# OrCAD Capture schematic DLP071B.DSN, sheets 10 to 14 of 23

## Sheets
10 PAGE14 - TP, ARM JTAG, RESET: size A3
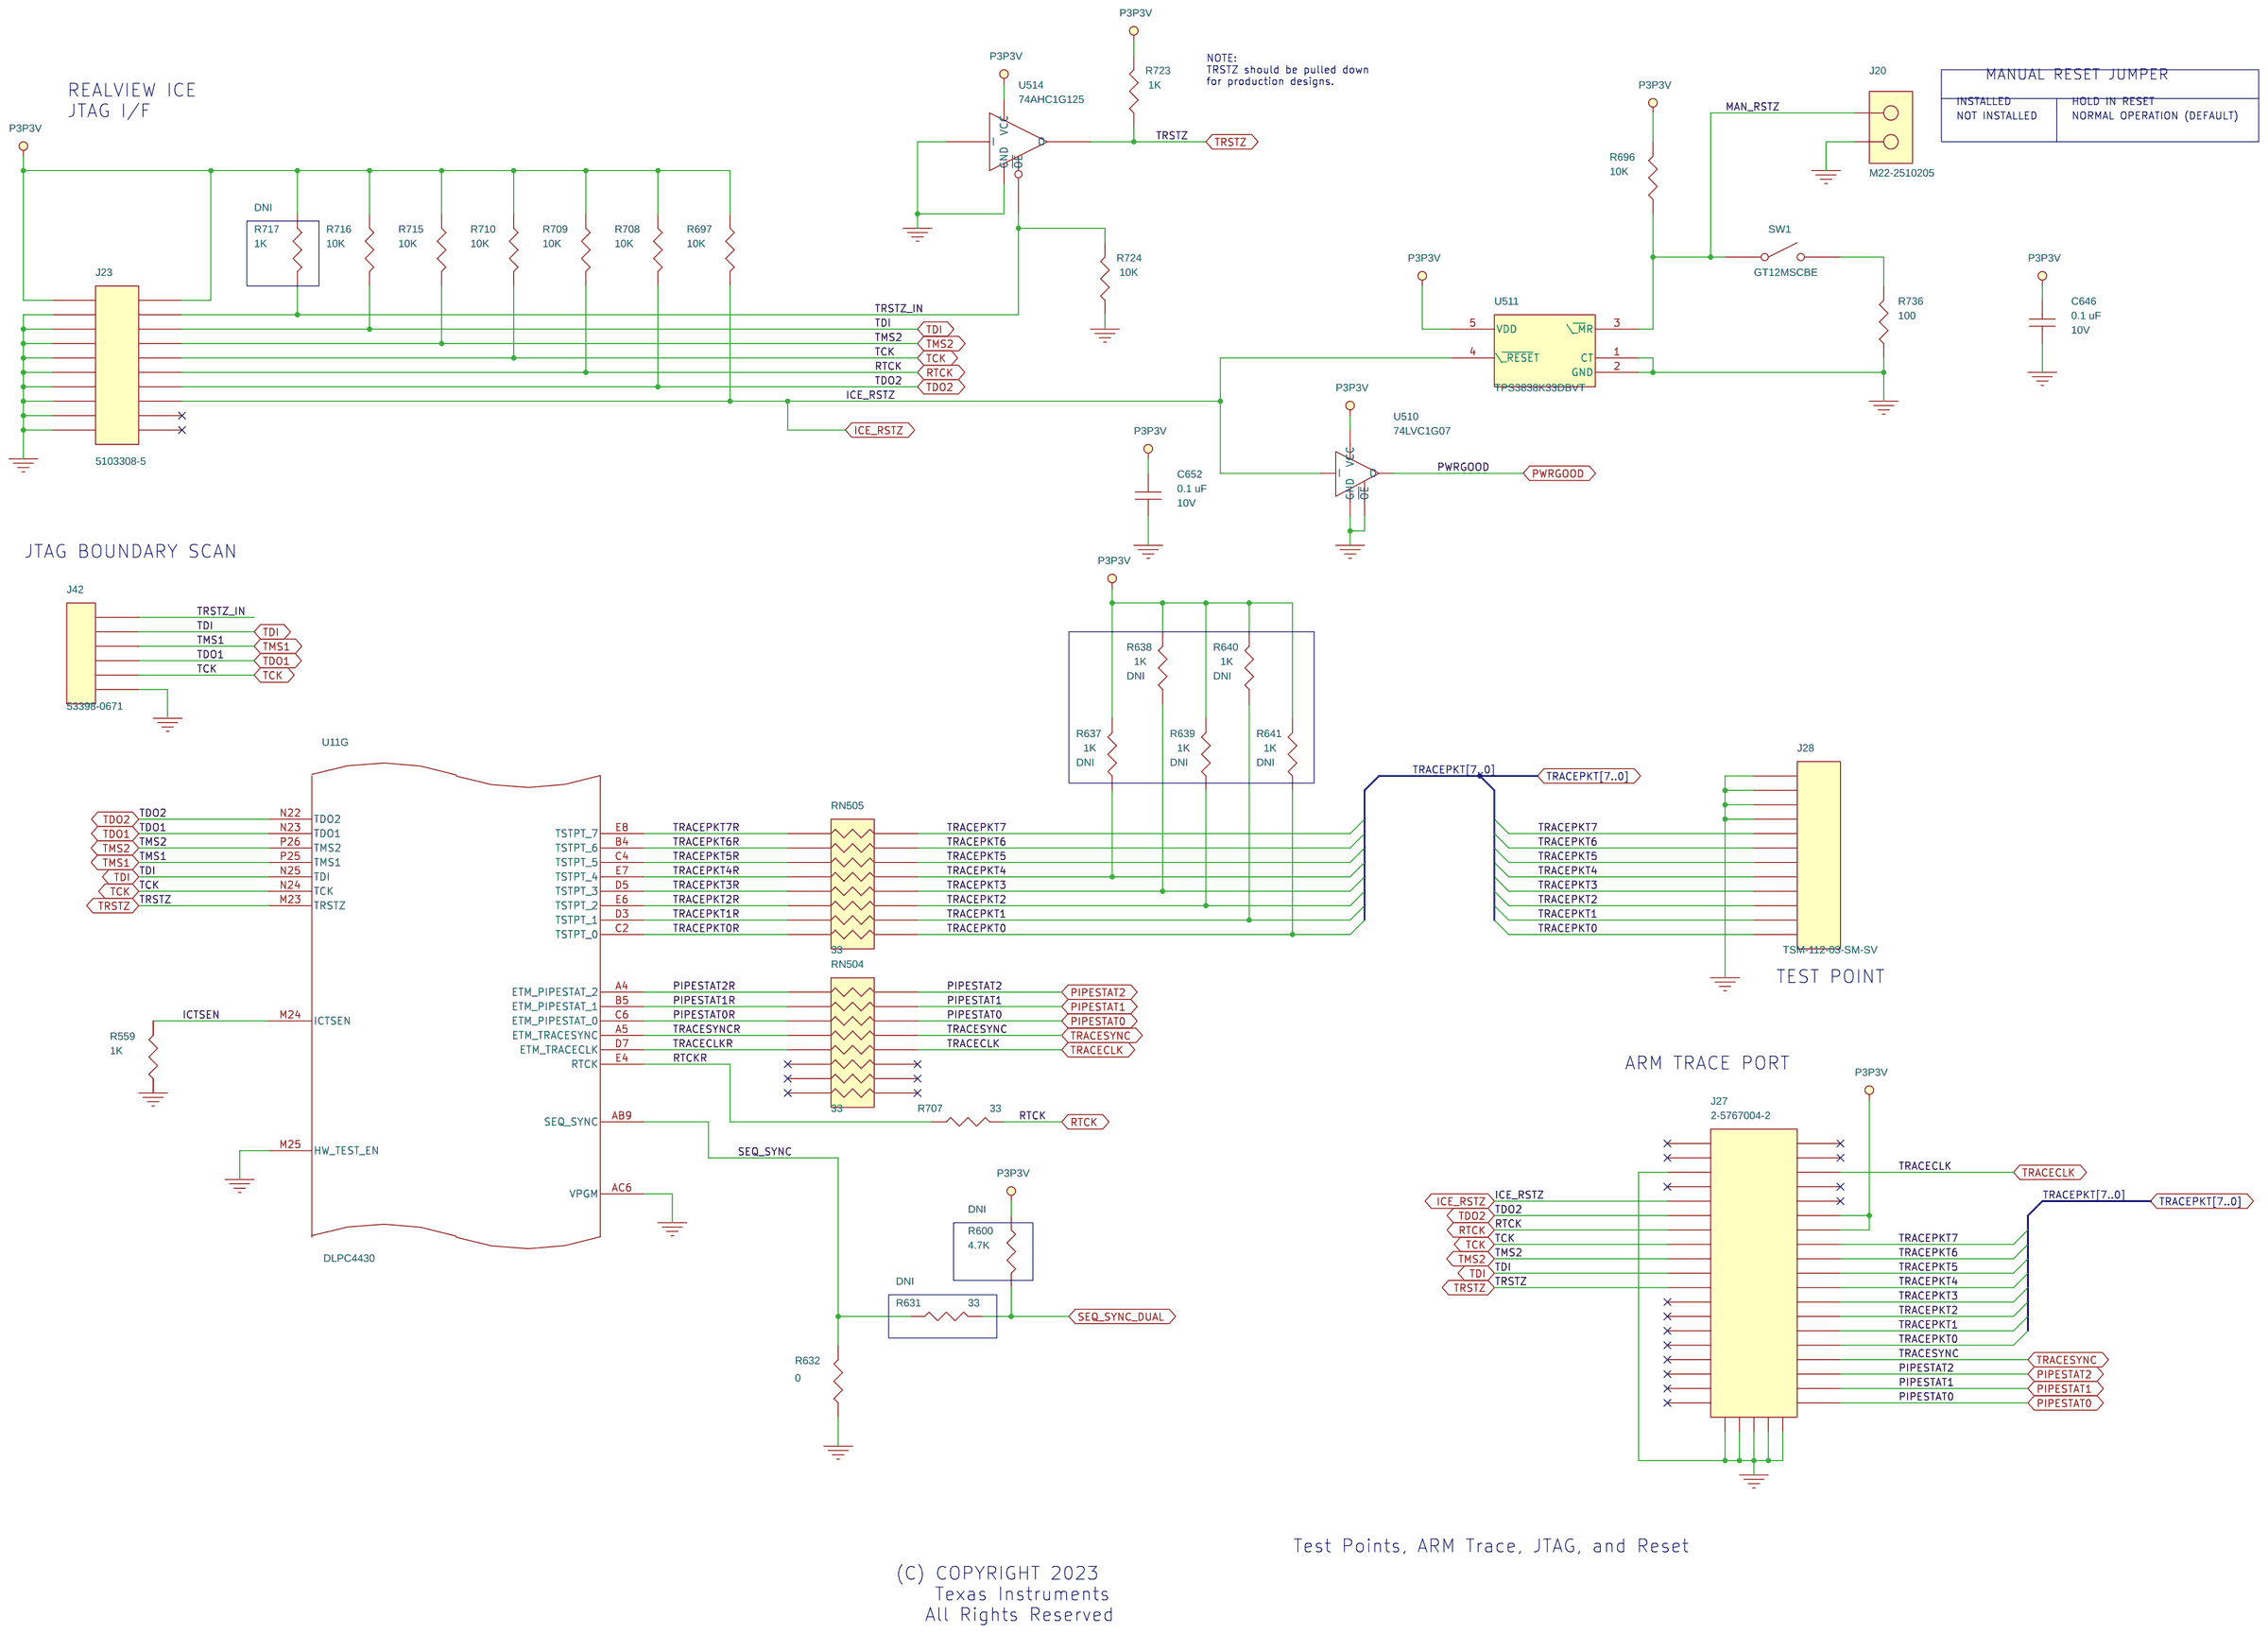
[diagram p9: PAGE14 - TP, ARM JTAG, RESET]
11 PAGE13 - GPIO EXP & KEYBRD: size A3
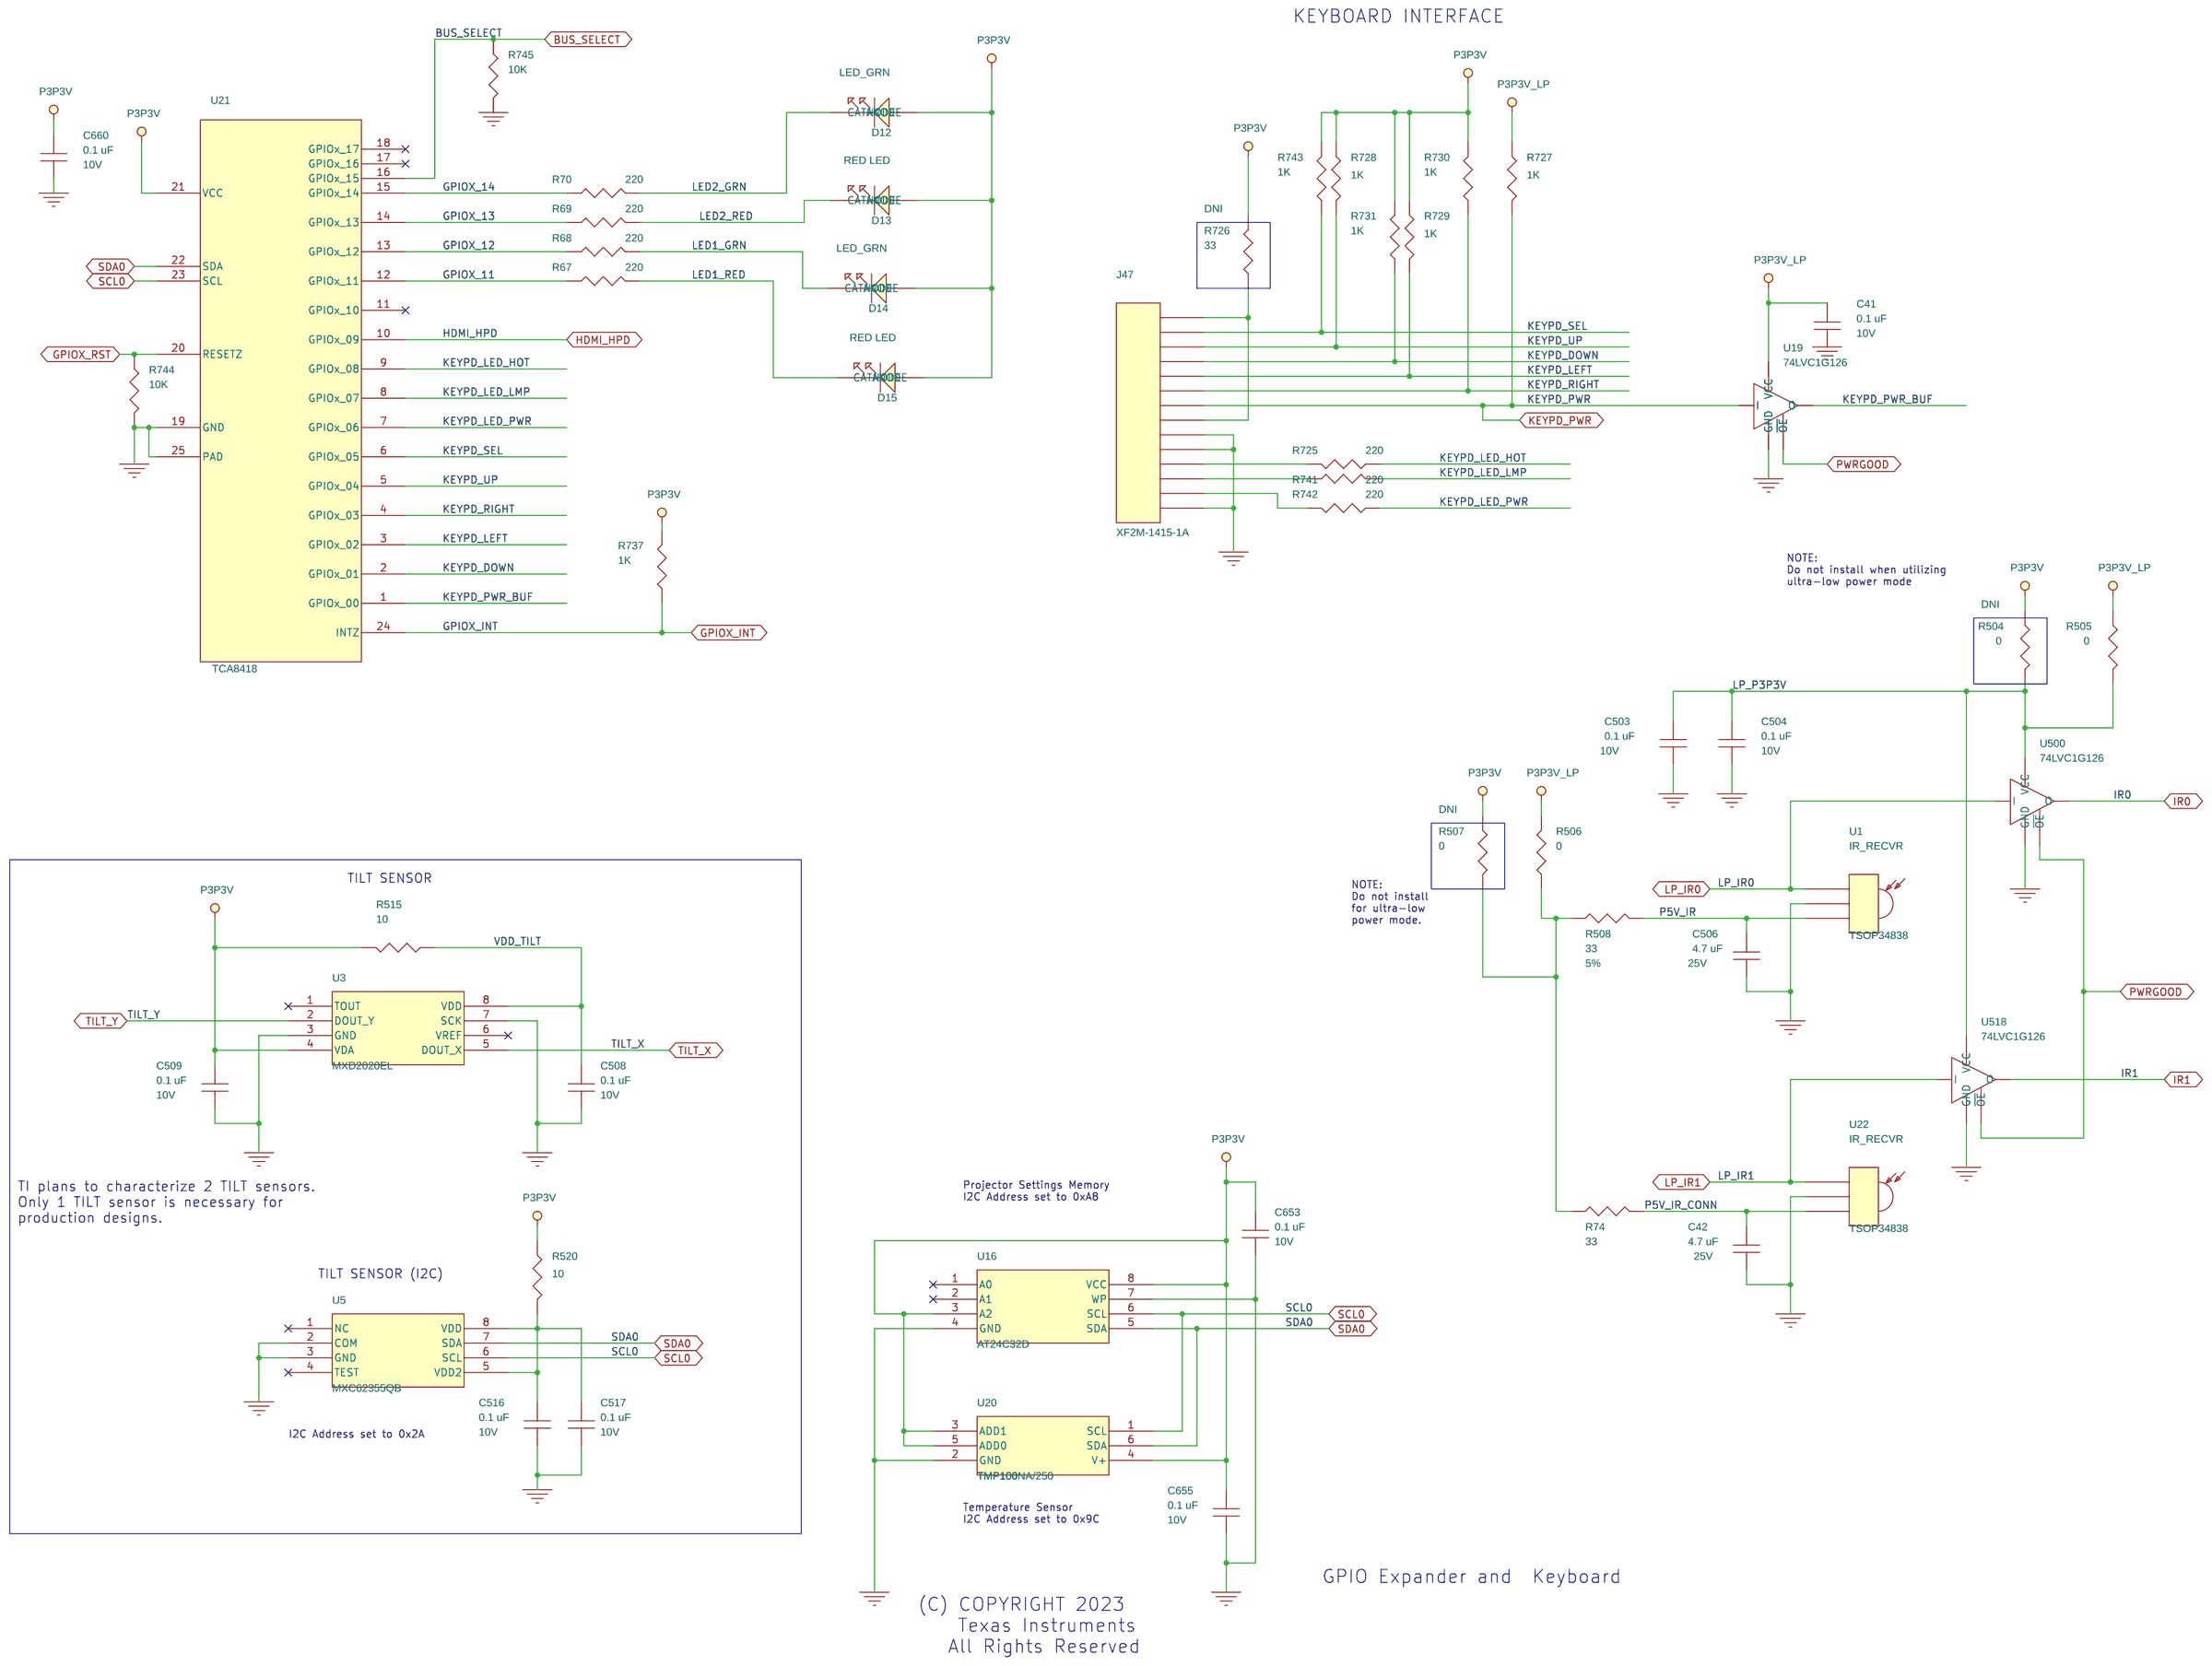
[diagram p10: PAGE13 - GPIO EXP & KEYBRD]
12 PAGE12 - GPIO, I2C, BALLAST: size A3
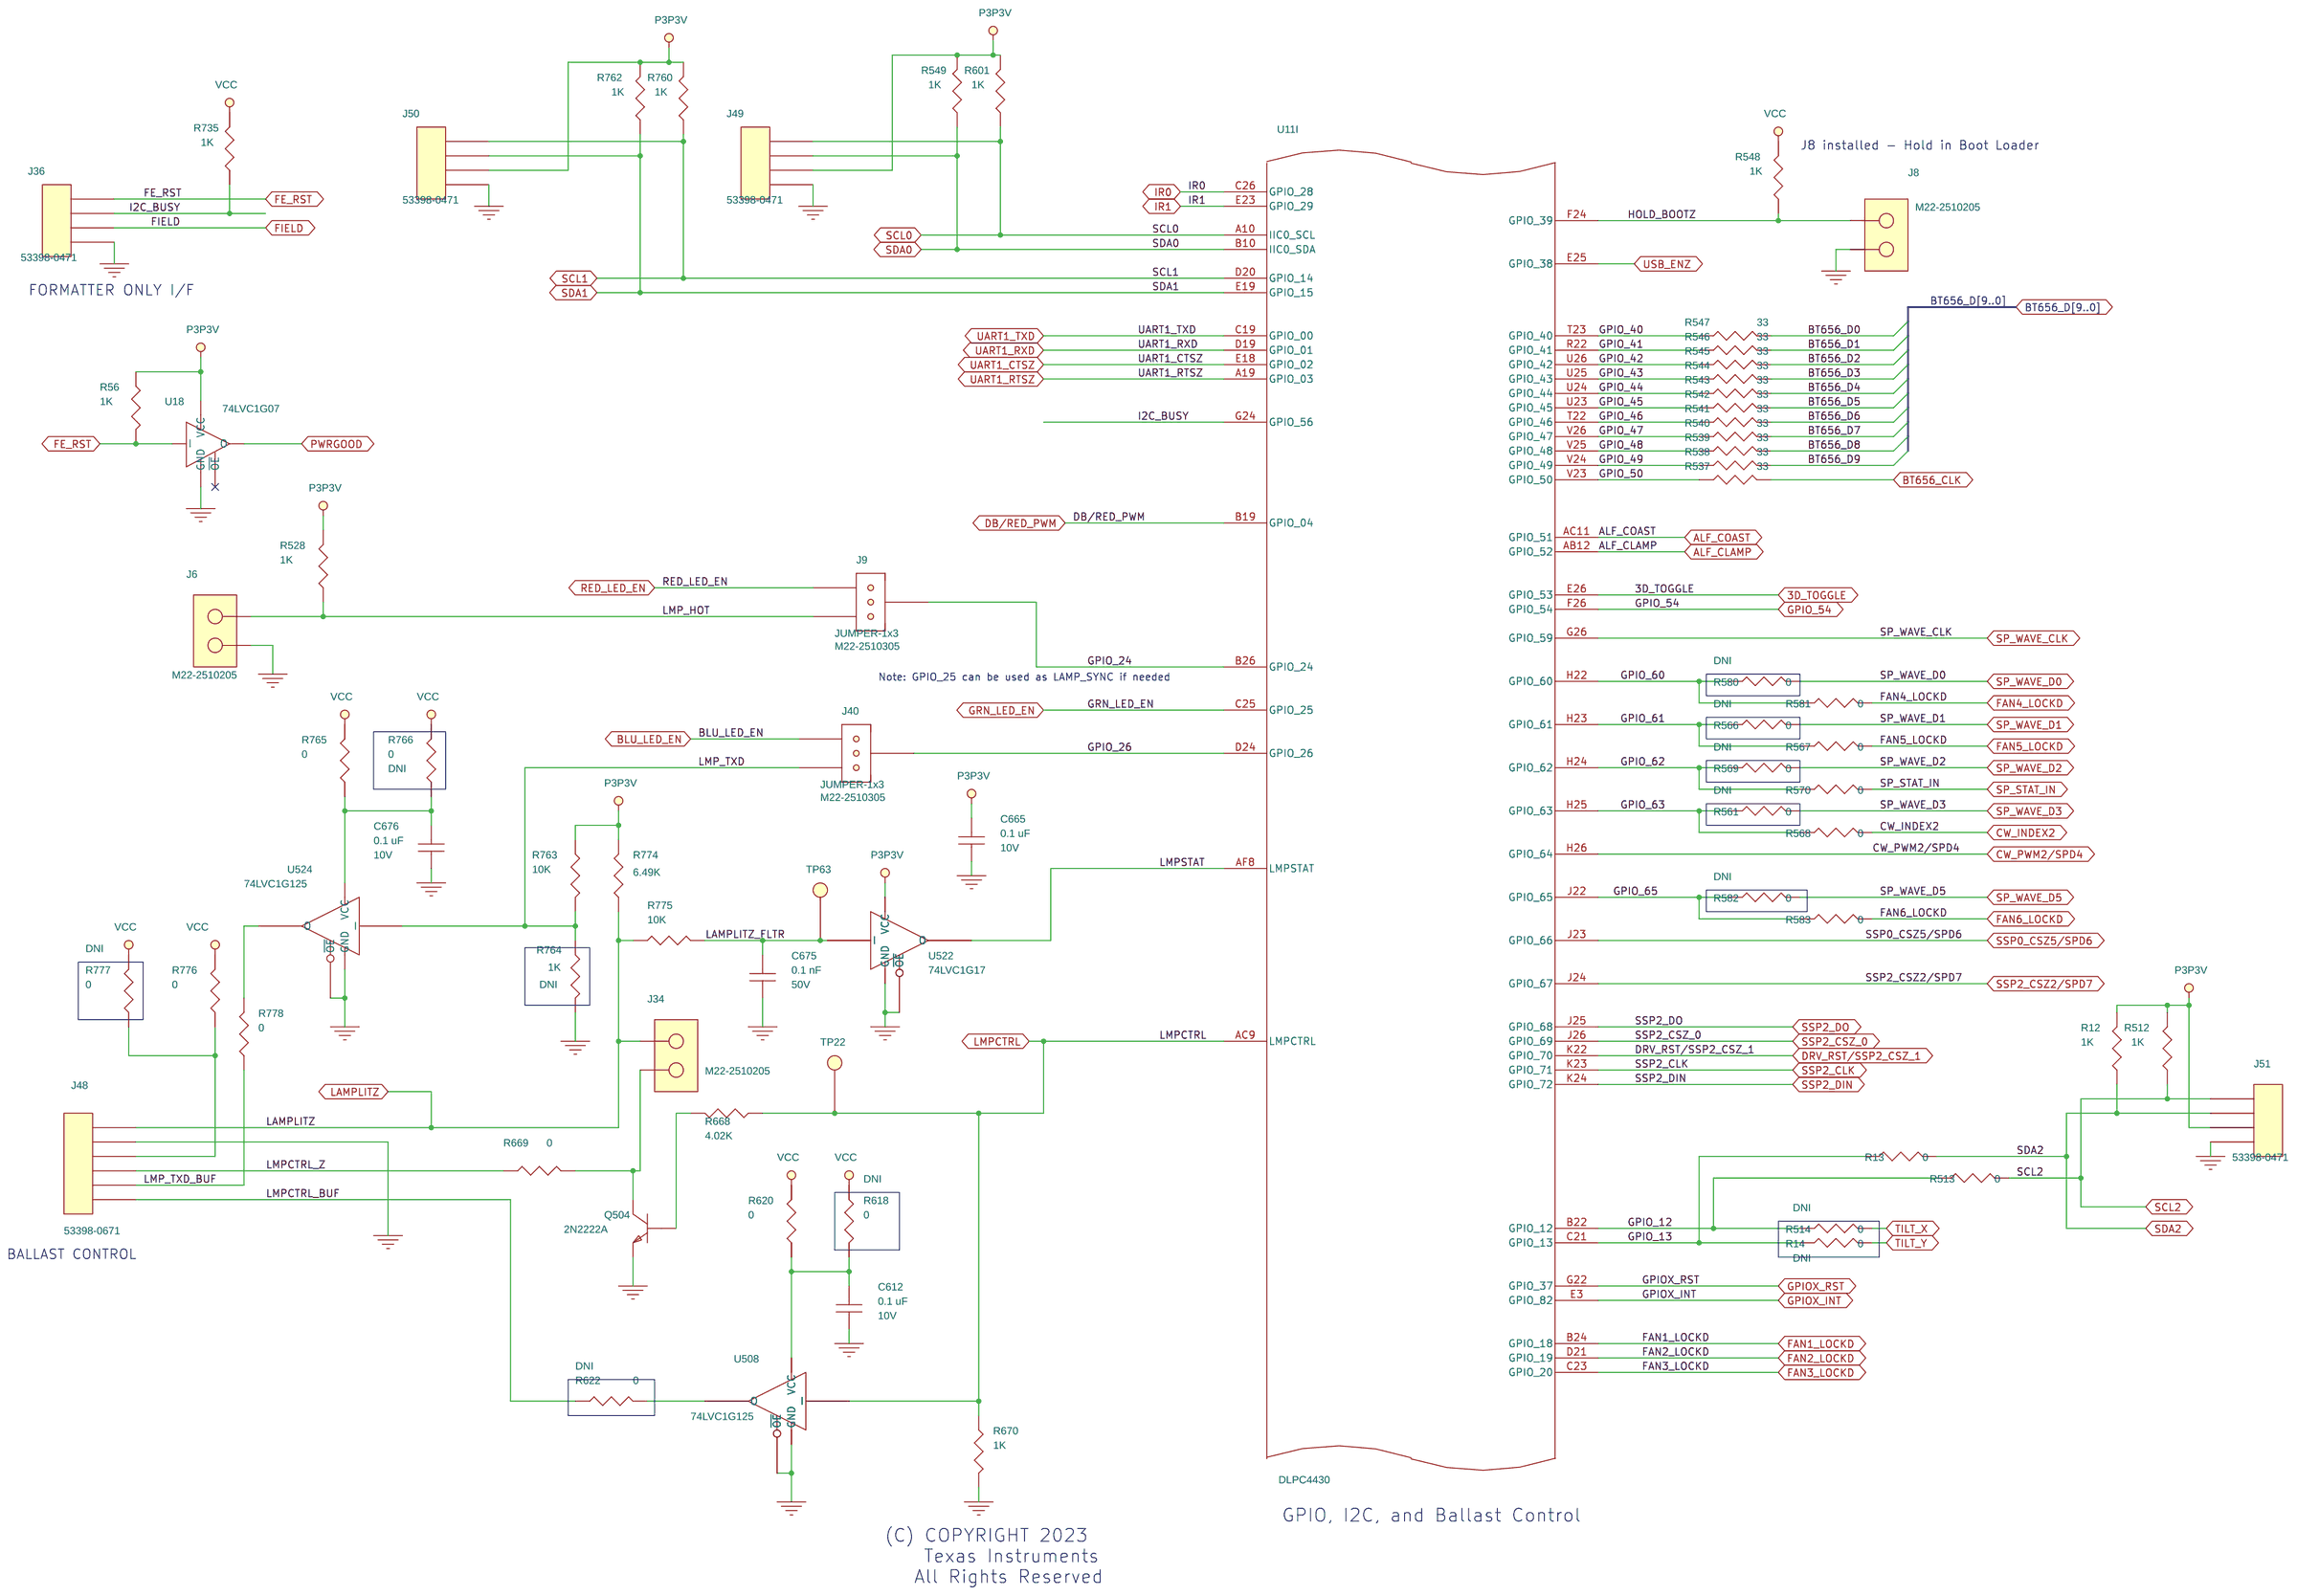
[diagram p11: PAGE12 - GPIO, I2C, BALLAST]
13 PAGE11 - FAN, CW INT & PERIPHLS: size A3
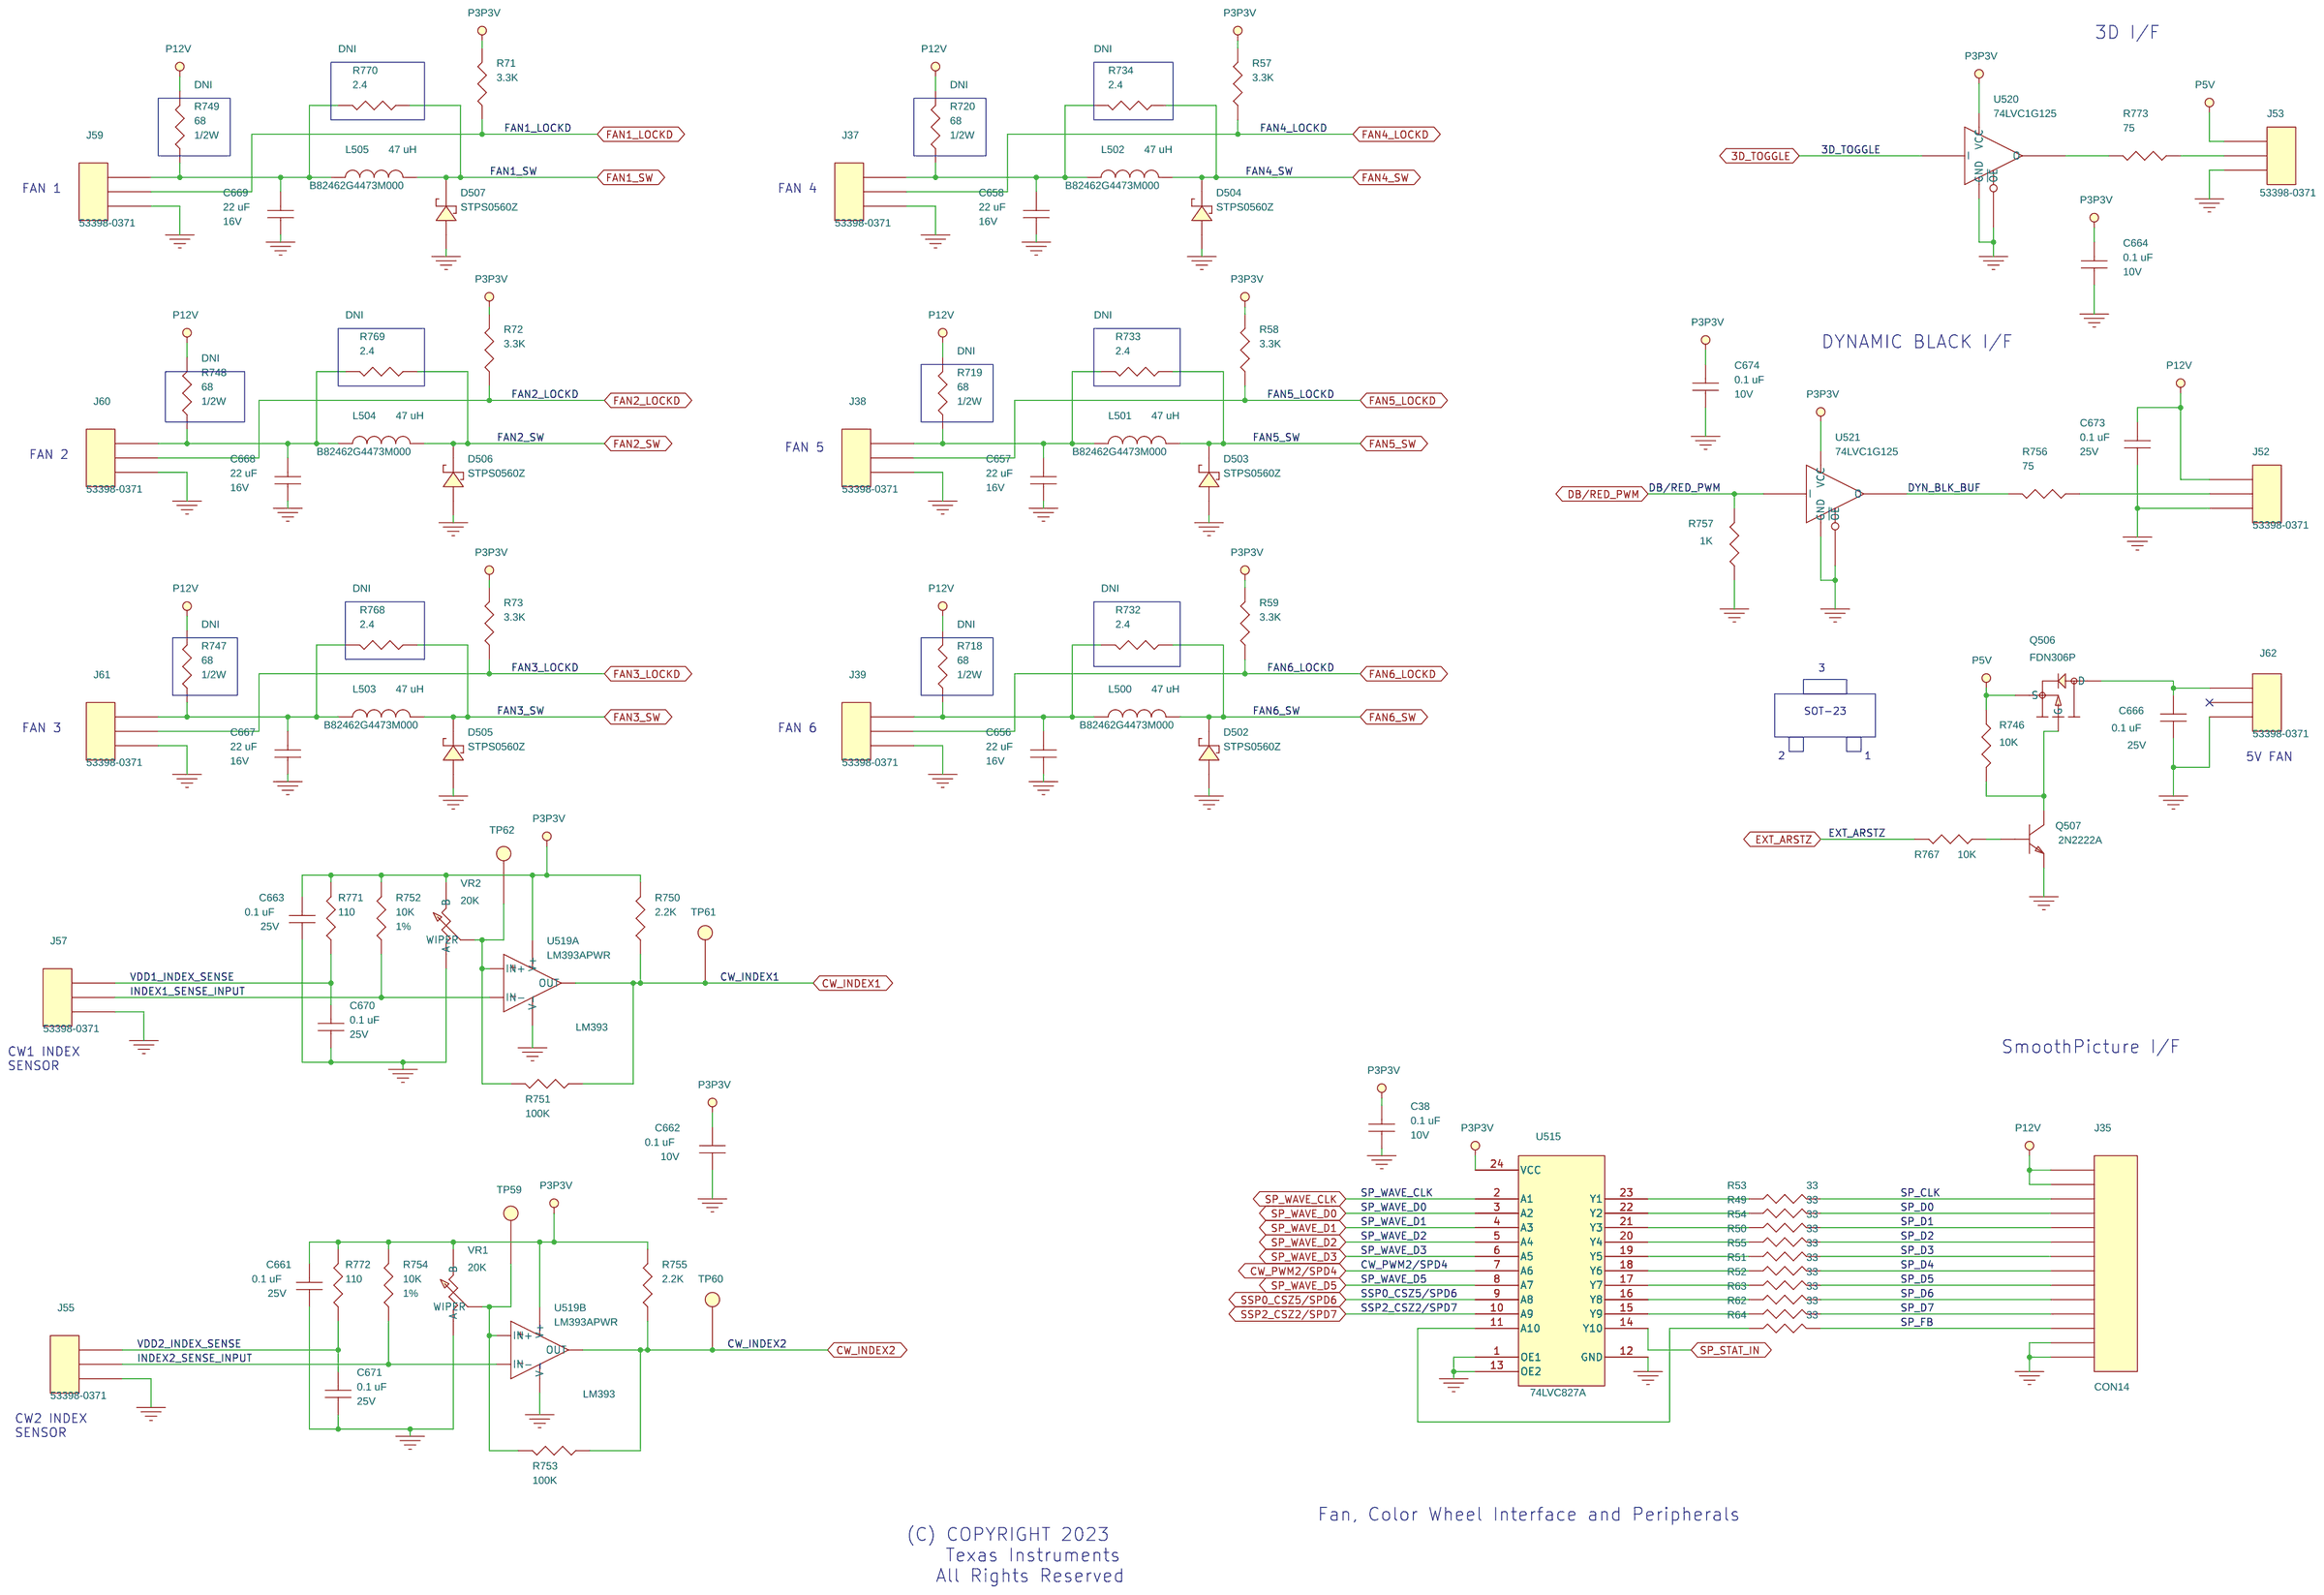
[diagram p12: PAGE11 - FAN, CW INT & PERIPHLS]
14 PAGE10 - COLOR WHEEL DRIVE: size A3
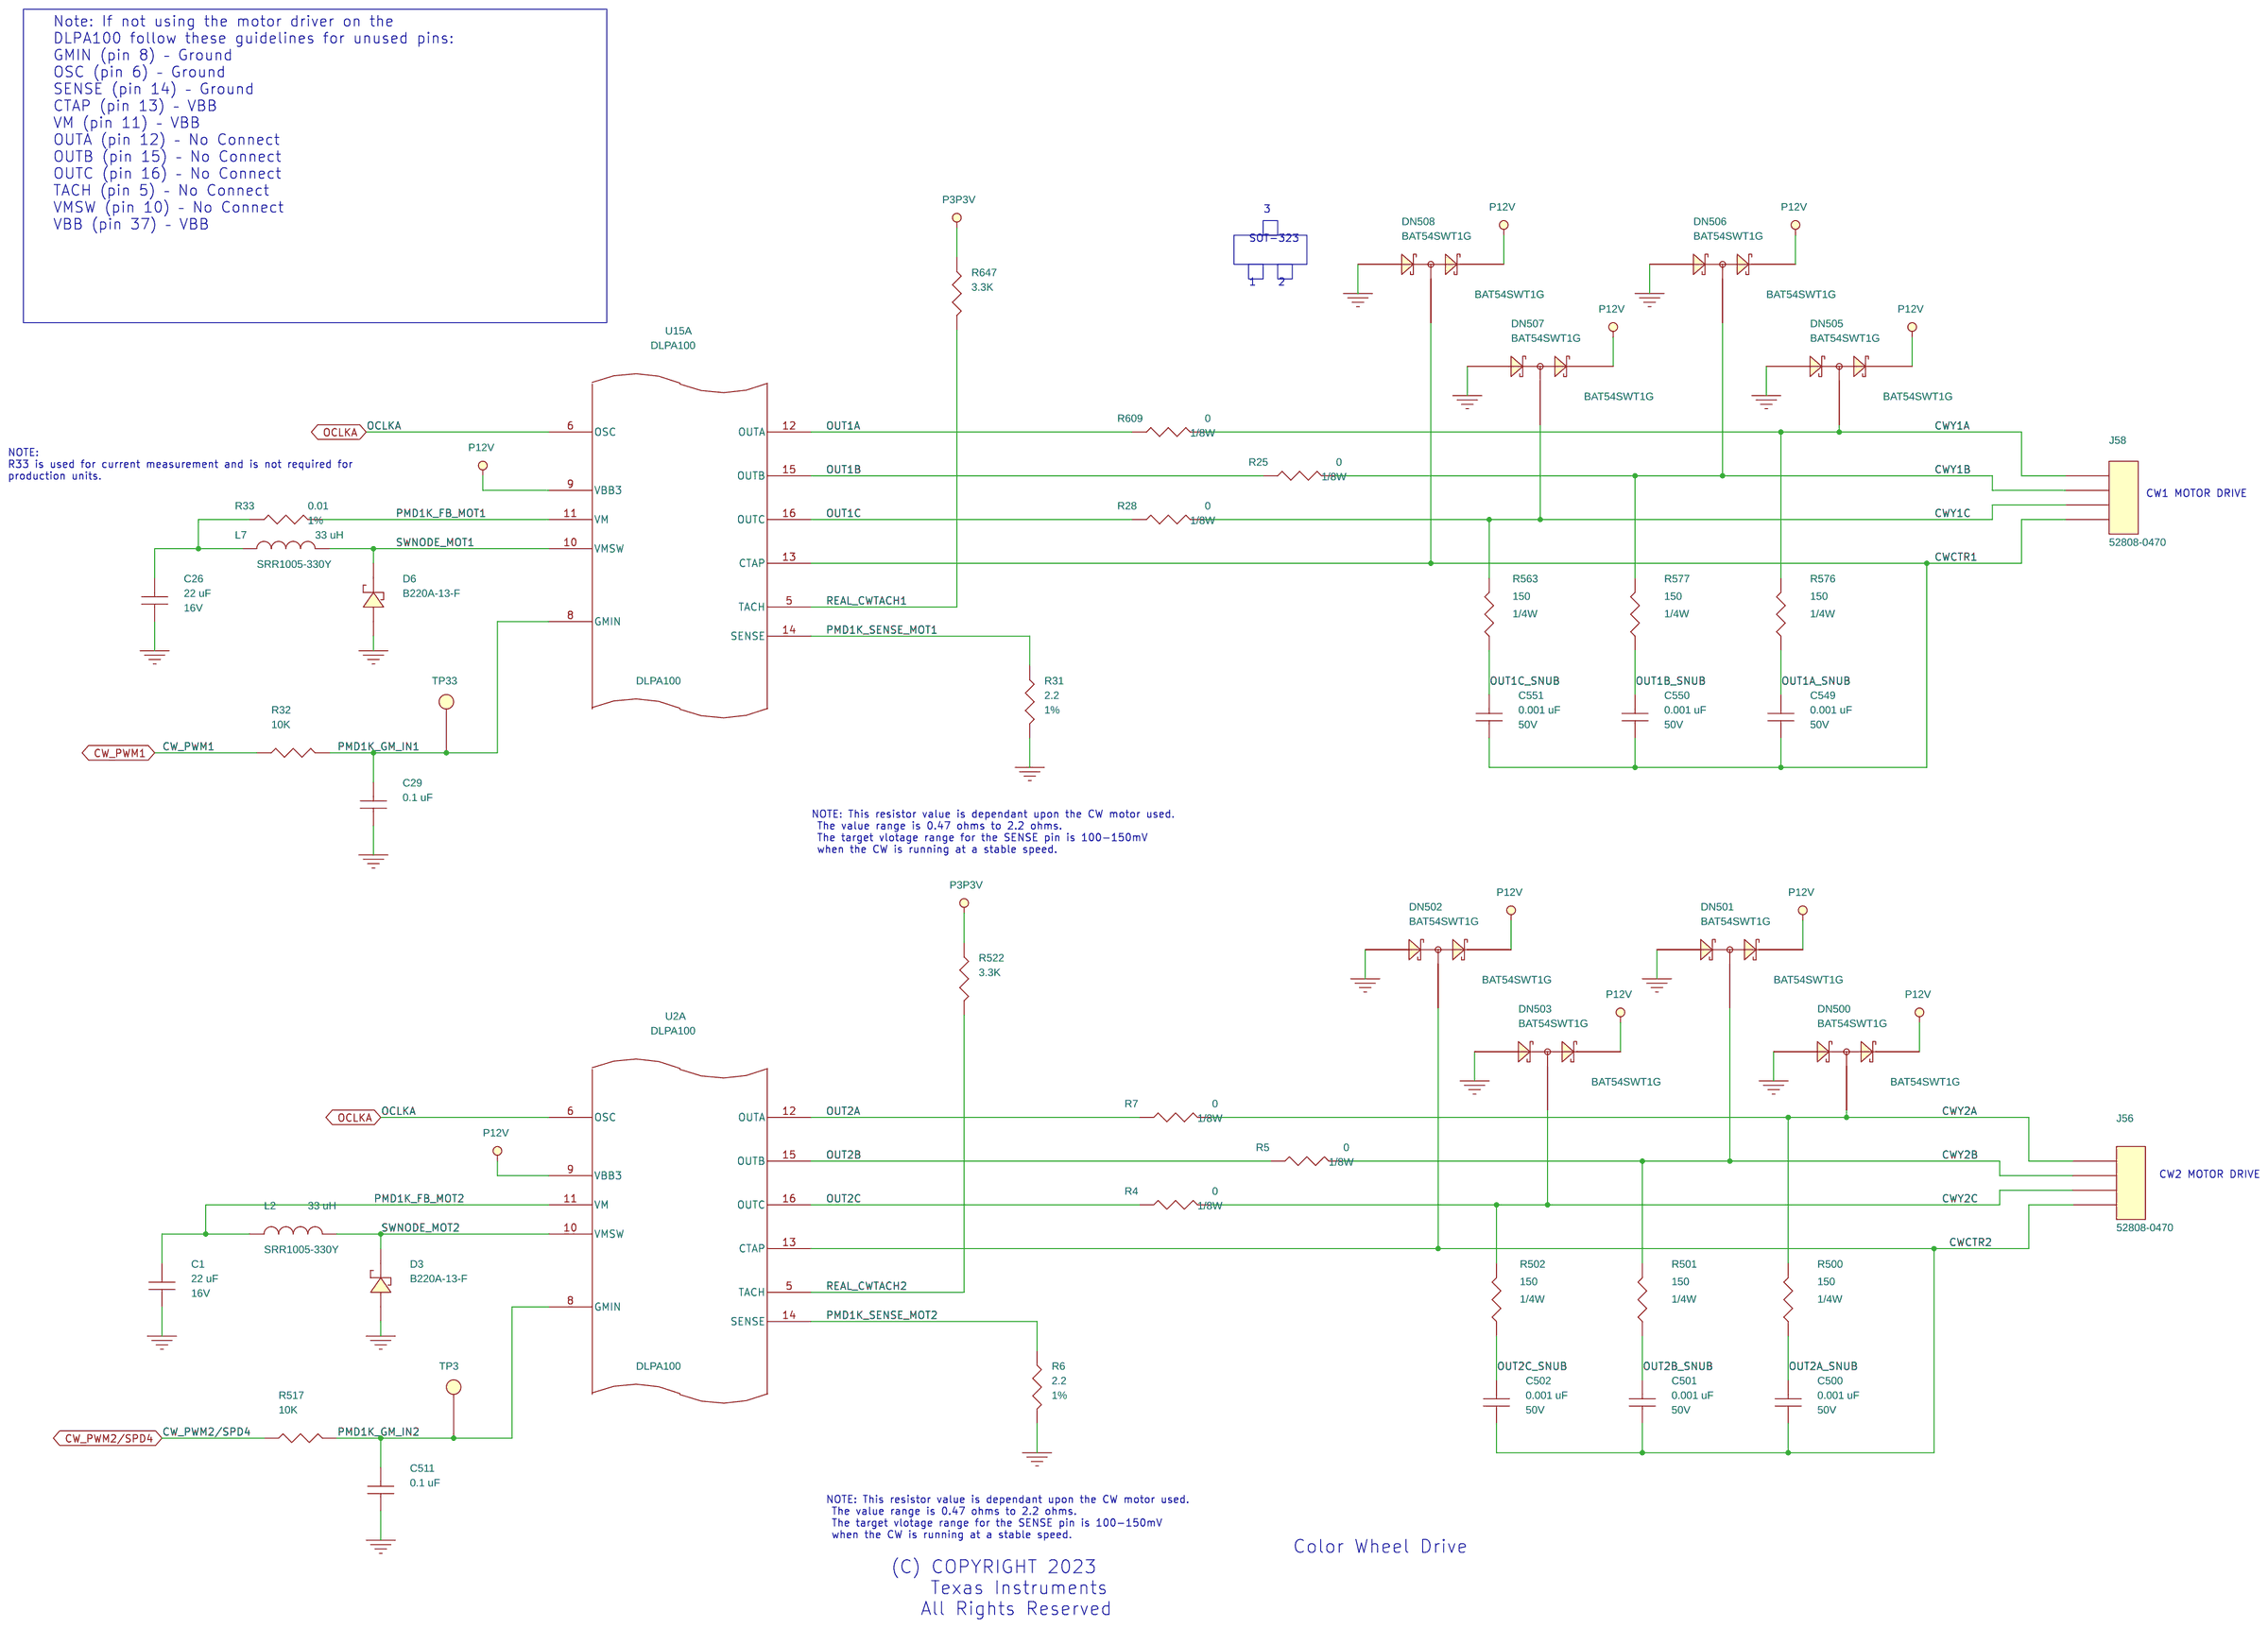
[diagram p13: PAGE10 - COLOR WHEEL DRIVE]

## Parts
sheet PAGE08 - DLPA100 POWER SUPPLIES
U15  DLPA100  [QF48_PPAD]  (sections A,B,C)
sheet PAGE09 - 2ND PMD POWER SUPPLIES
U2  DLPA100  [QF48_PPAD]  (sections A,B,C)
sheet PAGE10 - COLOR WHEEL DRIVE
C1  22 uF  [CAP_1210]
C26  22 uF  [CAP_1210]
C29  0.1 uF  [CAP_0402]
C500  0.001 uF  [CAP_0805]
C501  0.001 uF  [CAP_0805]
C502  0.001 uF  [CAP_0805]
C511  0.1 uF  [CAP_0402]
C549  0.001 uF  [CAP_0805]
C550  0.001 uF  [CAP_0805]
C551  0.001 uF  [CAP_0805]
D3  B220A  [DIO-SMA]
D6  B220A  [DIO-SMA]
DN500  BAT54SWT1G  [SOT_323]
DN501  BAT54SWT1G  [SOT_323]
DN502  BAT54SWT1G  [SOT_323]
DN503  BAT54SWT1G  [SOT_323]
DN505  BAT54SWT1G  [SOT_323]
DN506  BAT54SWT1G  [SOT_323]
DN507  BAT54SWT1G  [SOT_323]
DN508  BAT54SWT1G  [SOT_323]
J56  CON4  [CONN4-52808_MOLEX]
J58  CON4  [CONN4-52808_MOLEX]
L2  33 uH  [IND_SRR1005]
L7  33 uH  [IND_SRR1005]
R4  0  [RES_0805]
R5  0  [RES_0805]
R6  2.2  [RES_1206]
R7  0  [RES_0805]
R25  0  [RES_0805]
R28  0  [RES_0805]
R31  2.2  [RES_1206]
R32  10K  [RES_0402]
R33  0.01  [RES_0805]
R500  150  [RES_1206]
R501  150  [RES_1206]
R502  150  [RES_1206]
R517  10K  [RES_0402]
R522  3.3K  [RES_0402]
R563  150  [RES_1206]
R576  150  [RES_1206]
R577  150  [RES_1206]
R609  0  [RES_0805]
R647  3.3K  [RES_0402]
TP3  Testpoint  [TP]
TP33  Testpoint  [TP]
sheet PAGE11 - FAN, CW INT & PERIPHLS
C38  0.1 uF  [CAP_0402]
C656  22 uF  [CAP_1210]
C657  22 uF  [CAP_1210]
C658  22 uF  [CAP_1210]
C661  0.1 uF  [CAP_0603]
C662  0.1 uF  [CAP_0402]
C663  0.1 uF  [CAP_0603]
C664  0.1 uF  [CAP_0402]
C666  0.1 uF  [CAP_0603]
C667  22 uF  [CAP_1210]
C668  22 uF  [CAP_1210]
C669  22 uF  [CAP_1210]
C670  0.1 uF  [CAP_0603]
C671  0.1 uF  [CAP_0603]
C673  0.1 uF  [CAP_0603]
C674  0.1 uF  [CAP_0402]
D502  STPS0560Z  [SOD-123]
D503  STPS0560Z  [SOD-123]
D504  STPS0560Z  [SOD-123]
D505  STPS0560Z  [SOD-123]
D506  STPS0560Z  [SOD-123]
D507  STPS0560Z  [SOD-123]
J35  CON14  [CONN14-53047_MLX]
J37  CON3  [CN3_53398_MOLEX]
J38  CON3  [CN3_53398_MOLEX]
J39  CON3  [CN3_53398_MOLEX]
J52  CON3  [CN3_53398_MOLEX]
J53  CON3  [CN3_53398_MOLEX]
J55  CON3  [CN3_53398_MOLEX]
J57  CON3  [CN3_53398_MOLEX]
J59  CON3  [CN3_53398_MOLEX]
J60  CON3  [CN3_53398_MOLEX]
J61  CON3  [CN3_53398_MOLEX]
J62  CON3  [CN3_53398_MOLEX]
L500  47 uH  [IND_SERH]
L501  47 uH  [IND_SERH]
L502  47 uH  [IND_SERH]
L503  47 uH  [IND_SERH]
L504  47 uH  [IND_SERH]
L505  47 uH  [IND_SERH]
Q506  FDN306P  [SOT23-3_FC]
Q507  2N2222A  [SOT23AVXD]
R49  33  [RES_0402]
R50  33  [RES_0402]
R51  33  [RES_0402]
R52  33  [RES_0402]
R53  33  [RES_0402]
R54  33  [RES_0402]
R55  33  [RES_0402]
R57  3.3K  [RES_0402]
R58  3.3K  [RES_0402]
R59  3.3K  [RES_0402]
R62  33  [RES_0402]
R63  33  [RES_0402]
R64  33  [RES_0402]
R71  3.3K  [RES_0402]
R72  3.3K  [RES_0402]
R73  3.3K  [RES_0402]
R718  68  [RES_1210]
R719  68  [RES_1210]
R720  68  [RES_1210]
R732  2.4  [RES_1210]
R733  2.4  [RES_1210]
R734  2.4  [RES_1210]
R746  10K  [RES_0402]
R747  68  [RES_1210]
R748  68  [RES_1210]
R749  68  [RES_1210]
R750  2.2K  [RES_0603]
R751  100K  [RES_0402]
R752  10K  [RES_0402]
R753  100K  [RES_0402]
R754  10K  [RES_0402]
R755  2.2K  [RES_0603]
R756  75  [RES_0603]
R757  1K  [RES_0402]
R767  10K  [RES_0402]
R768  2.4  [RES_1210]
R769  2.4  [RES_1210]
R770  2.4  [RES_1210]
R771  110  [RES_0805]
R772  110  [RES_0805]
R773  75  [RES_0603]
TP59  Testpoint  [TP]
TP60  Testpoint  [TP]
TP61  Testpoint  [TP]
TP62  Testpoint  [TP]
U515  74LVC827A  [SOIC24-PW_TI]
U519  LM393  [SOIC8-PW_TI]  (sections A,B)
U520  74LVC1G125  [SOT23-DBV_TI]
U521  74LVC1G125  [SOT23-DBV_TI]
VR1  20K  [POT-3314G]
VR2  20K  [POT-3314G]
sheet PAGE12 - GPIO, I2C, BALLAST
C612  0.1 uF  [CAP_0402]
C665  0.1 uF  [CAP_0402]
C675  0.1 nF  [CAP_0603]
C676  0.1 uF  [CAP_0402]
J6  HDR_2  [HDR2_2MM]
J8  HDR_2  [HDR2_2MM]
J9  JUMPER-1x3  [HDR1X3-TMM1030X-X-S_SAM]
J34  HDR_2  [HDR2_2MM]
J36  CONN_4  [CONN4-53398-a_MOLEX]
J40  JUMPER-1x3  [HDR1X3-TMM1030X-X-S_SAM]
J48  CON6  [CONN6-53398-0690-a_MOLEX]
J49  CONN_4  [CONN4-53398-a_MOLEX]
J50  CONN_4  [CONN4-53398-a_MOLEX]
J51  CONN_4  [CONN4-53398-a_MOLEX]
Q504  2N2222A  [SOT23AVXD]
R12  1K  [RES_0402]
R13  0  [RES_0402]
R14  0  [RES_0402]
R56  1K  [RES_0402]
R512  1K  [RES_0402]
R513  0  [RES_0402]
R514  0  [RES_0402]
R528  1K  [RES_0402]
R537  33  [RES_0402]
R538  33  [RES_0402]
R539  33  [RES_0402]
R540  33  [RES_0402]
R541  33  [RES_0402]
R542  33  [RES_0402]
R543  33  [RES_0402]
R544  33  [RES_0402]
R545  33  [RES_0402]
R546  33  [RES_0402]
R547  33  [RES_0402]
R548  1K  [RES_0402]
R549  1K  [RES_0402]
R561  0  [RES_0402]
R566  0  [RES_0402]
R567  0  [RES_0402]
R568  0  [RES_0402]
R569  0  [RES_0402]
R570  0  [RES_0402]
R580  0  [RES_0402]
R581  0  [RES_0402]
R582  0  [RES_0402]
R583  0  [RES_0402]
R601  1K  [RES_0402]
R618  0  [RES_0402]
R620  0  [RES_0402]
R622  0  [RES_0402]
R668  4.02K  [RES_0603]
R669  0  [RES_0402]
R670  1K  [RES_0402]
R735  1K  [RES_0402]
R760  1K  [RES_0402]
R762  1K  [RES_0402]
R763  10K  [RES_0402]
R764  1K  [RES_0402]
R765  0  [RES_0402]
R766  0  [RES_0402]
R774  6.49K  [RES_0402]
R775  10K  [RES_0402]
R776  0  [RES_0402]
R777  0  [RES_0402]
R778  0  [RES_0402]
TP22  Testpoint  [TP]
TP63  Testpoint  [TP]
U18  74LVC1G07  [SOT23-DBV_TI]
U508  74LVC1G125  [SOT23-DBV_TI]
U522  74LVC1G17  [SOT23-DBV_TI]
U524  74LVC1G125  [SOT23-DBV_TI]
sheet PAGE13 - GPIO EXP & KEYBRD
C41  0.1 uF  [CAP_0402]
C42  4.7 uF  [CAP_0805]
C503  0.1 uF  [CAP_0402]
C504  0.1 uF  [CAP_0402]
C506  4.7 uF  [CAP_0805]
C508  0.1 uF  [CAP_0402]
C509  0.1 uF  [CAP_0402]
C516  0.1 uF  [CAP_0402]
C517  0.1 uF  [CAP_0402]
C653  0.1 uF  [CAP_0402]
C655  0.1 uF  [CAP_0402]
C660  0.1 uF  [CAP_0402]
D12  LED_GRN  [LED-0402-REV]
D13  RED LED  [LED-0402-REV]
D14  LED_GRN  [LED-0402-REV]
D15  RED LED  [LED-0402-REV]
J47  CON14  [conn14-xf2m-a_omron]
R67  220  [RES_0603]
R68  220  [RES_0603]
R69  220  [RES_0603]
R70  220  [RES_0603]
R74  33  [RES_0402]
R504  0  [RES_0402]
R505  0  [RES_0402]
R506  0  [RES_0402]
R507  0  [RES_0402]
R508  33  [RES_0402]
R515  10  [RES_0603]
R520  10  [RES_0603]
R725  220  [RES_0603]
R726  33  [RES_0402]
R727  1K  [RES_0402]
R728  1K  [RES_0402]
R729  1K  [RES_0402]
R730  1K  [RES_0402]
R731  1K  [RES_0402]
R737  1K  [RES_0402]
R741  220  [RES_0603]
R742  220  [RES_0603]
R743  1K  [RES_0402]
R744  10K  [RES_0402]
R745  10K  [RES_0402]
U1  IR_RECVR  [VISHAY_IR_TSOP348]
U3  TILT  [LCC8-MXD2125_MEMSIC]
U5  TILT_I2C  [LCC8-MXD2125_MEMSIC]
U16  AT24C32D  [TSSOP_8]
U19  74LVC1G126  [SOT23-DBV_TI]
U20  TMP100  [SOIC6-DBV_TI]
U21  TCA8418  [PQFP24-QFN-25_SI]
U22  IR_RECVR  [VISHAY_IR_TSOP348]
U500  74LVC1G126  [SOT23-DBV_TI]
U518  74LVC1G126  [SOT23-DBV_TI]
sheet PAGE14 - TP, ARM JTAG, RESET
C646  0.1 uF  [CAP_0402]
C652  0.1 uF  [CAP_0402]
J20  HDR_2  [HDR2_2MM]
J23  CON20A  [HDR10X2-5103308_TYCO]
J27  ARM_TRACE_PORT  [MICTOR_HPA]
J28  CON12  [CONN12-SMT-TSM-112-SV_SAMTEC]
J42  CON6  [CONN6-53398-0690-a_MOLEX]
R559  1K  [RES_0402]
R600  4.7K  [RES_0402]
R631  33  [RES_0402]
R632  0  [RES_0402]
R637  1K  [RES_0402]
R638  1K  [RES_0402]
R639  1K  [RES_0402]
R640  1K  [RES_0402]
R641  1K  [RES_0402]
R696  10K  [RES_0402]
R697  10K  [RES_0402]
R707  33  [RES_0402]
R708  10K  [RES_0402]
R709  10K  [RES_0402]
R710  10K  [RES_0402]
R715  10K  [RES_0402]
R716  10K  [RES_0402]
R717  1K  [RES_0402]
R723  1K  [RES_0402]
R724  10K  [RES_0402]
R736  100  [RES_0402]
RN504  33  [RNET16-EXB-2HV_PAN]
RN505  33  [RNET16-EXB-2HV_PAN]
SW1  SW SPST  [SW_GT12]
U510  74LVC1G07  [SOT23-DBV_TI]
U511  TPS3838  [SOT23-DBV_TI]
U514  74AHC1G125  [SOT23-DBV_TI]
sheet PAGE15 - RS-232, SSP, USB
U11  DLPC4430  [BGA552-DDP4422_TI_MOD]  (sections A,B,C,D,E,F,G,H,I,J)

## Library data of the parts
U2 U15 = PMD1000_0: IC, Power and Motor Driver; MFG: TI; SOURCE: PROVIDED BY TI
C1 C26 C656-C658 C667-C669 = CAP_NP: Capacitor; MFG: MURATA; Part Number: GRM32ER61C226KE20L; RATING: 16V; SOURCE: DIGI 490-1882-2-ND; TOLERANCE: 10%; Type: X5R
C29 C38 C41 C503 C504 C508 C509 C511 C516 C517 C612 C646 C652 C653 C655 C660 C662 C664 C665 C674 C676 = CAP_NP: Capacitor; MFG: KEMET; Part Number: C0402C104K8RACTU; RATING: 10V; SOURCE: DIGI 399-3520-1-ND; TOLERANCE: 10%; Type: X7R
C500-C502 C549-C551 = CAP_NP: Capacitor; MFG: AVX; Part Number: 08055C102KAT2A; RATING: 50V; SOURCE: DIGI 478-1371-1-ND; TOLERANCE: 10%; Type: X7R
D3 D6 = DIODE_SCHOTTKY: Diode, Schottky; MFG: DIODES INC; Part Number: B220A-13-F; RATING: 20V, 2A; SOURCE: DIGI B220A-FDICT-ND
DN500-DN503 DN505-DN507 = DS_DUAL_S_AJK_1: Diode, Schottky, Dual; MFG: ON SEMI; RATING: 30V, 200mA; SOURCE: DIGI BAT54SWT1GOSCT-ND
DN508 = DS_DUAL_S_AJK_0: Diode, Schottky, Dual; MFG: ON SEMI; RATING: 30V, 200mA; SOURCE: DIGI BAT54SWT1GOSCT-ND
J56 J58 = CON4: Connector, 4 pin, ribbon; MFG: MOLEX; Part Number: 52808-0470; SOURCE: MOUSER 538-52808-0470
L2 L7 = INDUCTOR: Inductor; ICA_MFR_NAME: STEWARD; ICA_PARTNUM: $$731362$$MI0603J680R-10; MFG: BOURNS; Part Number: SRR1005-330Y; RATING: 1.2A; SOURCE: DIGI SRR1005-330Y-ND; TOLERANCE: 15%
R4 R5 R7 R25 R28 R609 = R: Resistor; ICA_MFR_NAME: PANASONIC; ICA_PARTNUM: $$1785048$$ERJ-3GSYJ102; MFG: PANASONIC; Part Number: ERJ-6GEY0R00V; RATING: 1/8W; SOURCE: DIGI P0.0ACT-ND
R6 R31 = R: Resistor; ICA_MFR_NAME: PANASONIC; ICA_PARTNUM: $$1785048$$ERJ-3GSYJ102; MFG: PANASONIC; Part Number: ERJ-8RQF2R2V; RATING: 1/4W; SOURCE: DIGI P2.2RCT-ND; TOLERANCE: 1%
R32 R517 R696 R697 R708-R710 R715 R716 R724 R744-R746 R752 R754 R763 R767 R775 = R: Resistor; ICA_MFR_NAME: PANASONIC; ICA_PARTNUM: $$1785048$$ERJ-3GSYJ102; MFG: PANASONIC; Part Number: ERJ-2RKF1002X; RATING: 1/10W; SOURCE: DIGI P10.0KLCT-ND; TOLERANCE: 1%
R33 = R: Resistor; ICA_MFR_NAME: PANASONIC; ICA_PARTNUM: $$1785048$$ERJ-3GSYJ102; MFG: VISHAY/DALE; Part Number: WSL0805R0100FEA; RATING: 1/8W; SOURCE: DIGI WSLA-.01CT-ND; TOLERANCE: 1%
R500-R502 R563 R576 R577 = R: Resistor; ICA_MFR_NAME: PANASONIC; ICA_PARTNUM: $$1785048$$ERJ-3GSYJ102; MFG: PANASONIC; Part Number: ERJ-P08J151V; RATING: 1/4W; SOURCE: DIGI P150ALCT-ND; TOLERANCE: 5%
R57-R59 R71-R73 R522 R647 = R: Resistor; ICA_MFR_NAME: PANASONIC; ICA_PARTNUM: $$1785048$$ERJ-3GSYJ102; MFG: PANASONIC; Part Number: ERJ-2GEJ332X; RATING: 1/10W; SOURCE: DIGI P3.3KJCT-ND; TOLERANCE: 5%
TP3 TP22 TP33 TP59-TP63 = Testpoint: Test point
C661 C663 C666 C670 C671 C673 = CAP_NP: Capacitor; MFG: YAGEO; Part Number: CC0603KRX7R8BB104; RATING: 25V; SOURCE: DIGI PCC2277CT-ND; TOLERANCE: 10%; Type: X7R
D502-D507 = DIODE_SCHOTTKY: Diode, Schottky; MFG: STMICRO; RATING: 60V, 500mA; SOURCE: DIGI 497-3787-1-ND
J35 = CON14: MFG: MOLEX; Part Number: 53047-1410
J37-J39 J52 J53 J55 J57 J59-J62 = CON3: Connector, 3 pin; MFG: MOLEX; Part Number: 53398-0371; SOURCE: DIGI WM7607CT-ND
L500-L505 = INDUCTOR: Inductor; ICA_MFR_NAME: STEWARD; ICA_PARTNUM: $$731362$$MI0603J680R-10; MFG: EPCOS - TDK Electronics; Part Number: B82462G4473M000; RATING: 750mA; SOURCE: DIGI 495-1998-2-ND; TOLERANCE: 20%
Q506 = FDN306P_0: MOSFET, P-Channel; MFG: ON SEMI; SOURCE: DIGI FDN306PCT-ND
Q504 Q507 = 2N2222A: Transistor, NPN; MFG: FAIRCHILD; Part Number: MMBT2222A; RATING: 40V, 500mA; SOURCE: DIGI MMBT2222AFSCT-ND
R49-R55 R62-R64 R537-R547 = R: Resistor; MFG: PANASONIC; Part Number: ERJ-2GEJ330X; RATING: 1/10W; SOURCE: DIGI P33JCT-ND; TOLERANCE: 5%
R718-R720 R747-R749 = R: Resistor; DNI: DNI; ICA_MFR_NAME: PANASONIC; ICA_PARTNUM: $$1785048$$ERJ-3GSYJ102; MFG: PANASONIC; Part Number: ERJ-P14J680U; RATING: 1/2W; SOURCE: DIGI P68ASCT-ND; TOLERANCE: 5%
R732-R734 R768-R770 = R: Resistor; DNI: DNI; ICA_MFR_NAME: PANASONIC; ICA_PARTNUM: $$1785048$$ERJ-3GSYJ102; MFG: PANASONIC; Part Number: ERJ-14YJ2R4U; RATING: 1/2W; SOURCE: DIGI P2.4VTR-ND; TOLERANCE: 5%
R750 R755 = R: Resistor; ICA_MFR_NAME: PANASONIC; ICA_PARTNUM: $$1785048$$ERJ-3GSYJ102; MFG: PANASONIC; Part Number: ERJ-3GEYJ222V; RATING: 1/10W; SOURCE: DIGI P2.2KGCT-ND; TOLERANCE: 5%
R751 R753 = R: Resistor; ICA_MFR_NAME: PANASONIC; ICA_PARTNUM: $$1785048$$ERJ-3GSYJ102; MFG: PANASONIC; Part Number: ERJ-2GEJ104X; RATING: 1/10W; SOURCE: DIGI P100KJCT-ND; TOLERANCE: 5%
R756 R773 = R: Resistor; ICA_MFR_NAME: PANASONIC; ICA_PARTNUM: $$1785048$$ERJ-3GSYJ102; MFG: PANASONIC; Part Number: ERJ-3EKF75R0V; RATING: 1/10W; SOURCE: DIGI P75.0HCT-ND; TOLERANCE: 1%
R12 R56 R512 R528 R548 R549 R559 R601 R670 R723 R727-R731 R735 R737 R743 R757 R760 R762 = R: Resistor; ICA_MFR_NAME: PANASONIC; ICA_PARTNUM: $$1785048$$ERJ-3GSYJ102; MFG: PANASONIC; Part Number: ERJ-2GEJ102X; RATING: 1/10W; SOURCE: DIGI P1.0KJCT-ND; TOLERANCE: 5%
R771 R772 = R: Resistor; ICA_MFR_NAME: PANASONIC; ICA_PARTNUM: $$1785048$$ERJ-3GSYJ102; MFG: PANASONIC; Part Number: ERJ-6GEYJ111V; RATING: 1/8W; SOURCE: DIGI P110ACT-ND; TOLERANCE: 5%
U515 = 74LVC827A: IC, 10 Ch Buffer; MFG: TI; Part Number: SN74LVC827APWR; SOURCE: DIGI 296-8548-1-ND
U519 = OPAMP_DUAL_9: IC, Comparator; MFG: TI; Part Number: LM393APWR; SOURCE: DIGI 296-6610-1-ND
U520 = 74LVC1G125_1: IC, Non-Inverting Buffer, Tri-State; MFG: TI; Part Number: SN74LVC1G125DBVR; SOURCE: DIGI 296-11603-1-ND
U508 U521 U524 = 74LVC1G125_2: IC, Non-Inverting Buffer, Tri-State; MFG: TI; Part Number: SN74LVC1G125DBVR; SOURCE: DIGI 296-11603-1-ND
VR1 = POT_R_S_4: IC, Potentiometer; MFG: BOURNS; Part Number: 3314G-1-203E; RATING: 1/4W; SOURCE: DIGI 3314G-203ETR-ND; TOLERANCE: 20%
VR2 = POT_R_S_3: IC, Potentiometer; MFG: BOURNS; Part Number: 3314G-1-203E; RATING: 1/4W; SOURCE: DIGI 3314G-203ETR-ND; TOLERANCE: 20%
C675 = CAP_NP: Capacitor; MFG: KEMET; Part Number: C0603C101J5GACTU; RATING: 50V; SOURCE: DIGI 399-1061-2-ND; TOLERANCE: 5%; Type: NP0
J6 J8 J20 J34 = HDR_2: Jumper, 1x2; MFG: HARWIN; Part Number: M22-2510205; SOURCE: DIGI 952-1311-ND
J9 J40 = JUMPER-1x3: Jumper, 1x3; MFG: HARWIN; Part Number: M22-2510305; SOURCE: DIGI 952-1312-ND
J36 J49-J51 = CONN_4: Connector, 4 pin; MFG: MOLEX; Part Number: 53398-0471; SOURCE: DIGI WM7608CT-ND
J42 J48 = CON6: Connector, 6 pin; MFG: MOLEX; Part Number: 53398-0671; SOURCE: DIGI WM7610CT-ND
R13 R505 R506 R513 R567 R568 R570 R581 R583 R620 R632 R669 R765 R776 R778 = R: Resistor; ICA_MFR_NAME: PANASONIC; ICA_PARTNUM: $$1785048$$ERJ-3GSYJ102; MFG: PANASONIC; Part Number: ERJ-2GE0R00X; RATING: 1/10W; SOURCE: DIGI P0.0JCT-ND
R14 R504 R507 R514 R561 R566 R569 R580 R582 R618 R622 R766 R777 = R: Resistor; DNI: DNI; ICA_MFR_NAME: PANASONIC; ICA_PARTNUM: $$1785048$$ERJ-3GSYJ102; MFG: PANASONIC; Part Number: ERJ-2GE0R00X; RATING: 1/10W; SOURCE: DIGI P0.0JCT-ND
R668 = R: Resistor; ICA_MFR_NAME: PANASONIC; ICA_PARTNUM: $$1785048$$ERJ-3GSYJ102; MFG: PANASONIC; Part Number: ERJ-3EKF4021V; RATING: 1/10W; SOURCE: DIGI P4.02KHCT-ND; TOLERANCE: 1%
R637-R641 R717 R764 = R: Resistor; DNI: DNI; ICA_MFR_NAME: PANASONIC; ICA_PARTNUM: $$1785048$$ERJ-3GSYJ102; MFG: PANASONIC; Part Number: ERJ-2GEJ102X; RATING: 1/10W; SOURCE: DIGI P1.0KJCT-ND; TOLERANCE: 5%
R774 = R: Resistor; ICA_MFR_NAME: PANASONIC; ICA_PARTNUM: $$1785048$$ERJ-3GSYJ102; MFG: PANASONIC; Part Number: ERJ-2RKF6491X; RATING: 1/10W; SOURCE: DIGI P6.49KLCT-ND; TOLERANCE: 1%
U18 = 74LVC1G07_0: IC, Non-Inverting Buffer, Open Drain; MFG: TI; Part Number: SN74LVC1G07DBVR; SOURCE: DIGI 296-8485-1-ND
U522 = 74LVC1G17_0: IC, Non-Inverting Schmitt-Trigger Buffer; MFG: TI; Part Number: SN74LVC1G17DBVR; SOURCE: DIGI 296-11933-1-ND
C42 C506 = CAP_NP: Capacitor; MFG: TDK; Part Number: C2012X7R1E475K; RATING: 25V; SOURCE: DIGI 445-5972-1-ND; TOLERANCE: 10%; Type: X7R
D12 D14 = LED_0: LED GREEN CLEAR 0402 SMD; Digikey Part Number: 67-1881-1-ND; MFG: LUMEX OPTO; Manuf Part Number: SML-LX0402SUGC-TR; Manufacturer: LUMEX OPTO; Manufacturer Part Number: SML-LX0402SUGC-TR; Part Number: SML-LX0402SUGC-TR
D13 D15 = LED_0: LED RED CLEAR 0402 SMD; Digikey Part Number: 67-1878-1-ND; MFG: LUMEX OPTO; Manuf Part Number: SML-LX0402SIC-TR; Manufacturer: LUMEX OPTO; Manufacturer Part Number: SML-LX0402SIC-TR; Part Number: SML-LX0402SIC-TR
J47 = CON14: Connector, 14 pin, ribbon; MFG: OMRON; Part Number: XF2M-1415-1A; SOURCE: DIGI OR755CT-ND
R67-R70 R725 R741 R742 = R: Resistor; ICA_MFR_NAME: PANASONIC; ICA_PARTNUM: $$1785048$$ERJ-3GSYJ102; MFG: PANASONIC; Part Number: ERJ-3GEYJ221V; RATING: 1/10W; SOURCE: DIGI P220GCT-ND; TOLERANCE: 5%
R74 R508 R707 = R: Resistor; ICA_MFR_NAME: PANASONIC; ICA_PARTNUM: $$1785048$$ERJ-3GSYJ102; MFG: PANASONIC; Part Number: ERJ-2GEJ330X; RATING: 1/10W; SOURCE: DIGI P33JCT-ND; TOLERANCE: 5%
R515 R520 = R: Resistor; ICA_MFR_NAME: PANASONIC; ICA_PARTNUM: $$1785048$$ERJ-3GSYJ102; MFG: PANASONIC; Part Number: ERJ-3GEYJ100V; RATING: 1/10W; SOURCE: DIGI P10GCT-ND; TOLERANCE: 5%
R631 R726 = R: Resistor; DNI: DNI; ICA_MFR_NAME: PANASONIC; ICA_PARTNUM: $$1785048$$ERJ-3GSYJ102; MFG: PANASONIC; Part Number: ERJ-2GEJ330X; RATING: 1/10W; SOURCE: DIGI P33JCT-ND; TOLERANCE: 5%
U1 U22 = IR_RECVR: IC, IR Receiver; MFG: VISHAY; Part Number: TSOP34838; SOURCE: VISHAY
U3 = TILT: IC, Accelerometer; Part Number: MXD2020EL; SOURCE: MEMSIC
U5 = TILT_I2C: IC, Accelerometer; Part Number: MXC62355QB; SOURCE: MEMSIC
U16 = EEPROM: IC, EEPROM, Serial; MFG: ATMEL; Part Number: AT24C32D-XHM-T; RATING: 32K; SOURCE: DIGI AT24C32D-XHM-T SL901CT-ND
U19 U500 U518 = 74LVC1G126: IC, Non-Inverting Buffer, Tri-State; MFG: TI; Part Number: SN74LVC1G126DBVR; SOURCE: DIGI 296-11605-1-ND
U20 = TEMP: IC, Temperature Sensor; MFG: TI; Part Number: TMP100NA/250; SOURCE: DIGI 296-12749-2-ND
U21 = TCA8418_0: IC, GPIO Expander; MFG: TI; Part Number: TCA8418RTWR; SOURCE: DIGI 296-25223-1-ND
J23 = CON20A: Connector, 20 pin; MFG: TE; Part Number: 5103308-5; SOURCE: DIGI A33165-ND
J27 = ARM_TRACE_PORT: Connector, 38 pin; ALT P/N: 2-767004-2; MFG: TYCO; Part Number: 2-5767004-2; SOURCE: TYCO
J28 = CON12: Header, 12 pin; MFG: SAMTEC; Part Number: TSM-112-03-SM-SV; SOURCE: SAMTEC
R600 = R: Resistor; DNI: DNI; ICA_MFR_NAME: PANASONIC; ICA_PARTNUM: $$1785048$$ERJ-3GSYJ102; MFG: PANASONIC; Part Number: ERJ-2GEJ472X; RATING: 1/10W; SOURCE: DIGI P4.7KJCT-ND; TOLERANCE: 5%
R736 = R: Resistor; ICA_MFR_NAME: PANASONIC; ICA_PARTNUM: $$1785048$$ERJ-3GSYJ102; MFG: PANASONIC; Part Number: ERJ-2GEJ101X; RATING: 1/10W; SOURCE: DIGI P100JCT-ND; TOLERANCE: 5%
RN504 RN505 = RESISTOR_DIP_8: Resistor Pack; MFG: PANASONIC; Part Number: EXB-2HV330JV; RATING: 1/16W; SOURCE: DIGI Y1330CT-ND; TOLERANCE: 5%
SW1 = SW_SPST_1: Switch; MFG: C&K COMPONENTS; Part Number: GT12MSCBE; SOURCE: DIGI CKN9050TR-ND
U510 = 74LVC1G07: IC, Non-Inverting Buffer, Open Drain; MFG: TI; Part Number: SN74LVC1G07DBVR; SOURCE: DIGI 296-8485-1-ND
U511 = TPS3838: IC, Supervisor; MFG: TI; Part Number: TPS3838K33DBVT; SOURCE: DIGI 296-3349-2-ND
U514 = 74AHC1G125_0: IC, Non-Inverting Buffer, Tri-State; MFG: TI; Part Number: SN74AHC1G125DBVR; SOURCE: DIGI 296-8744-1-ND
U11 = DDP442x: IC, ASIC; MFG: TI; SOURCE: PROVIDED BY TI

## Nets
GND: C1.1 C26.1 C29.1 C38.1 C41.1 C42.1 C503.1 C504.1 C506.1 C508.1 C509.1 C511.1 C516.1 C517.1 C612.1 C646.1 C652.1 C653.1 C655.1 C656.1 C657.1 C658.1 C660.1 C661.1 C662.1 C663.1 C664.1 C665.1 C666.1 C667.1 C668.1 C669.1 C670.1 C671.1 C673.1 C674.1 C675.1 C676.1 D3.2(A) D6.2(A) D502.2(A) D503.2(A) D504.2(A) D505.2(A) D506.2(A) D507.2(A) DN500.1 DN501.1 DN502.1 DN503.1 DN505.1 DN506.1 DN507.1 DN508.1 J6.2 J8.2 J20.2 J23.4 J23.6 J23.8 J23.10 J23.12 J23.14 J23.16 J23.18 J23.20 J27.5 J27.G1 J27.G2 J27.G3 J27.G4 J27.G5 J28.9 J28.10 J28.11 J28.12 J35.13 J35.14 J36.4 J37.3 J38.3 J39.3 J42.6 J47.9 J47.10 J47.14 J48.2 J49.4 J50.4 J51.4 J52.3 J53.3 J55.3 J57.3 J59.3 J60.3 J61.3 J62.3 Q504.1(EMITTER) Q507.1(EMITTER) R6.2 R31.2 R559.2 R632.1 R670.2 R724.1 R736.1 R744.2 R745.2 R757.1 R764.1 U1.2 U3.3(GND) U3.7(SCK) U5.2(COM) U5.3(GND) U11.AC6(VPGM) U11.M25(HW_TEST_EN) U16.4(GND) U16.7(WP) U18.3(GND) U19.3(GND) U20.2(GND) U21.19(GND) U21.25(PAD) U22.2 U500.3(GND) U508.1(~{OE}) U508.3(GND) U510.1(~{OE}) U510.3(GND) U511.1(CT) U511.2(GND) U514.2(I) U514.3(GND) U515.1(OE1) U515.12(GND) U515.13(OE2) U518.3(GND) U519.4(V-) U520.1(~{OE}) U520.3(GND) U521.1(~{OE}) U521.3(GND) U522.1(~{OE}) U522.3(GND) U524.1(~{OE}) U524.3(GND) VR1.1(A) VR2.1(A) ; also on sheet 1 4 5 6 7 8 9 15 16 17 18 20 21
P5V: J53.1 Q506.2(S) R618.1 R746.2 R766.1 R777.1 ; also on sheet 5 7 16 20 21
P5V_IR: C506.2 R508.1 U1.3
P5V_IR_CONN: C42.2 R74.1 U22.3
P12V: C673.2 DN500.2 DN501.2 DN502.2 DN503.2 DN505.2 DN506.2 DN507.2 DN508.2 J35.1 J35.2 J52.1 R718.2 R719.2 R720.2 R747.2 R748.2 R749.2 U2.9(VBB3) U15.9(VBB3) ; also on sheet 1 6 15 16 17 21
VDD1_INDEX_SENSE: C670.2 J57.1 R771.1
VDD2_INDEX_SENSE: C671.2 J55.1 R772.1
VDD_TILT: C508.2 R515.1 U3.8(VDD)
3D_TOGGLE: U11.E26(GPIO_53) U520.2(I) ; also on sheet 6
ALF_CLAMP: U11.AB12(GPIO_52) ; also on sheet 21
ALF_COAST: U11.AC11(GPIO_51) ; also on sheet 21
BLU_LED_EN: J40.1 ; also on sheet 6
BT656_CLK: R537.2 ; also on sheet 20
BT656_D0: R547.2 ; also on sheet 20
BT656_D1: R546.2 ; also on sheet 20
BT656_D2: R545.2 ; also on sheet 20
BT656_D3: R544.2 ; also on sheet 20
BT656_D4: R543.2 ; also on sheet 20
BT656_D5: R542.2 ; also on sheet 20
BT656_D6: R541.2 ; also on sheet 20
BT656_D7: R540.2 ; also on sheet 20
BT656_D8: R539.2 ; also on sheet 20
BT656_D9: R538.2 ; also on sheet 20
BUS_SELECT: R745.1 U21.16(GPIOx_15) ; also on sheet 21
CW_INDEX1: R750.1 R751.1 TP61.1 U519.1(OUT) ; also on sheet 17 20
CW_INDEX2: R568.2 R753.1 R755.1 TP60.1 U519.7(OUT)
CW_PWM1: R32.1 ; also on sheet 17
CW_PWM2/SPD4: R517.1 U11.H26(GPIO_64) U515.7(A6)
CWCTR1: C549.1 C550.1 C551.1 DN508.3 J58.1 U15.13(CTAP)
CWCTR2: C500.1 C501.1 C502.1 DN502.3 J56.1 U2.13(CTAP)
CWY1A: DN505.3 J58.4 R576.2 R609.2
CWY1B: DN506.3 J58.3 R25.2 R577.2
CWY1C: DN507.3 J58.2 R28.2 R563.2
CWY2A: DN500.3 J56.4 R7.2 R500.2
CWY2B: DN501.3 J56.3 R5.2 R501.2
CWY2C: DN503.3 J56.2 R4.2 R502.2
DB/RED_PWM: R757.2 U11.B19(GPIO_04) U521.2(I) ; also on sheet 6
DRV_RST/SSP2_CSZ_1: U11.K22(GPIO_70) ; also on sheet 6
DYN_BLK_BUF: R756.2 U521.4(O)
EXT_ARSTZ: R767.1 ; also on sheet 1 17 20
FAN1_LOCKD: J59.2 R71.1 U11.B24(GPIO_18)
FAN1_SW: D507.1(C) L505.2 R770.1 ; also on sheet 17
FAN2_LOCKD: J60.2 R72.1 U11.D21(GPIO_19)
FAN2_SW: D506.1(C) L504.2 R769.1 ; also on sheet 17
FAN3_LOCKD: J61.2 R73.1 U11.C23(GPIO_20)
FAN3_SW: D505.1(C) L503.2 R768.1 ; also on sheet 17
FAN4_LOCKD: J37.2 R57.1 R581.2
FAN4_SW: D504.1(C) L502.2 R734.1 ; also on sheet 15
FAN5_LOCKD: J38.2 R58.1 R567.2
FAN5_SW: D503.1(C) L501.2 R733.1 ; also on sheet 15
FAN6_LOCKD: J39.2 R59.1 R583.2
FAN6_SW: D502.1(C) L500.2 R732.1 ; also on sheet 15
FE_RST: J36.1 R56.2 U18.2(I)
FIELD: J36.3 ; also on sheet 19 21
GPIO_12: R513.1 R514.1 U11.B22(GPIO_12)
GPIO_13: R13.1 R14.1 U11.C21(GPIO_13)
GPIO_24: J9.2 U11.B26(GPIO_24)
GPIO_26: J40.2 U11.D24(GPIO_26)
GPIO_40: R547.1 U11.T23(GPIO_40)
GPIO_41: R546.1 U11.R22(GPIO_41)
GPIO_42: R545.1 U11.U26(GPIO_42)
GPIO_43: R544.1 U11.U25(GPIO_43)
GPIO_44: R543.1 U11.U24(GPIO_44)
GPIO_45: R542.1 U11.U23(GPIO_45)
GPIO_46: R541.1 U11.T22(GPIO_46)
GPIO_47: R540.1 U11.V26(GPIO_47)
GPIO_48: R539.1 U11.V25(GPIO_48)
GPIO_49: R538.1 U11.V24(GPIO_49)
GPIO_50: R537.1 U11.V23(GPIO_50)
GPIO_54: U11.F26(GPIO_54) ; also on sheet 6
GPIO_60: R580.1 R581.1 U11.H22(GPIO_60)
GPIO_61: R566.1 R567.1 U11.H23(GPIO_61)
GPIO_62: R569.1 R570.1 U11.H24(GPIO_62)
GPIO_63: R561.1 R568.1 U11.H25(GPIO_63)
GPIO_65: R582.1 R583.1 U11.J22(GPIO_65)
GPIOX_11: R67.1 U21.12(GPIOx_11)
GPIOX_12: R68.1 U21.13(GPIOx_12)
GPIOX_13: R69.1 U21.14(GPIOx_13)
GPIOX_14: R70.1 U21.15(GPIOx_14)
GPIOX_INT: R737.1 U11.E3(GPIO_82) U21.24(INTZ)
GPIOX_RST: R744.1 U11.G22(GPIO_37) U21.20(RESETZ)
GRN_LED_EN: U11.C25(GPIO_25) ; also on sheet 6
HDMI_HPD: U21.10(GPIOx_09) ; also on sheet 21
HOLD_BOOTZ: J8.1 R548.2 U11.F24(GPIO_39)
I2C_BUSY: J36.2 R735.2 U11.G24(GPIO_56)
ICE_RSTZ: J23.15 J27.9 R697.1 U510.2(I) U511.4(\~{_RESE}T)
ICTSEN: R559.1 U11.M24(ICTSEN)
INDEX1_SENSE_INPUT: J57.2 R752.1 U519.2(IN-)
INDEX2_SENSE_INPUT: J55.2 R754.1 U519.6(IN-)
IR0: U11.C26(GPIO_28) U500.4(O)
IR1: U11.E23(GPIO_29) U518.4(O)
KEYPD_DOWN: J47.4 R731.1 U21.2(GPIOx_01)
KEYPD_LED_HOT: R725.2 U21.9(GPIOx_08)
KEYPD_LED_LMP: R741.2 U21.8(GPIOx_07)
KEYPD_LED_PWR: R742.2 U21.7(GPIOx_06)
KEYPD_LEFT: J47.5 R729.1 U21.3(GPIOx_02)
KEYPD_PWR: J47.7 R727.1 U19.2(I) ; also on sheet 17
KEYPD_PWR_BUF: U19.4(O) U21.1(GPIOx_00)
KEYPD_RIGHT: J47.6 R730.1 U21.4(GPIOx_03)
KEYPD_SEL: J47.2 R743.1 U21.6(GPIOx_05)
KEYPD_UP: J47.3 R728.1 U21.5(GPIOx_04)
LAMPLITZ: J34.1 J48.1 R774.1 R775.1 ; also on sheet 6
LAMPLITZ_FLTR: C675.2 R775.2 TP63.1 U522.2(I)
LED1_GRN: D14.2(CATHODE) R68.2
LED1_RED: D15.2(CATHODE) R67.2
LED2_GRN: D12.2(CATHODE) R70.2
LED2_RED: D13.2(CATHODE) R69.2
LMP_HOT: J6.1 J9.3 R528.2
LMP_TXD: J40.3 R763.1 R764.2 U524.2(I)
LMP_TXD_BUF: J48.5 R778.1
LMPCTRL: R668.2 R670.1 TP22.1 U11.AC9(LMPCTRL) U508.2(I) ; also on sheet 6
LMPCTRL_BUF: J48.6 R622.1
LMPCTRL_Z: J48.4 R669.1
LMPSTAT: U11.AF8(LMPSTAT) U522.4(O)
LP_IR0: U1.1 U500.2(I) ; also on sheet 17
LP_IR1: U22.1 U518.2(I) ; also on sheet 17
LP_P3P3V: C503.2 C504.2 R504.1 R505.1 U500.5(VCC) U518.5(VCC)
MAN_RSTZ: J20.1 R696.1 SW1.3 U511.3(\~{_M}R)
OCLKA: U2.6(OSC) U15.6(OSC) ; also on sheet 17
OUT1A: R609.1 U15.12(OUTA)
OUT1A_SNUB: C549.2 R576.1
OUT1B: R25.1 U15.15(OUTB)
OUT1B_SNUB: C550.2 R577.1
OUT1C: R28.1 U15.16(OUTC)
OUT1C_SNUB: C551.2 R563.1
OUT2A: R7.1 U2.12(OUTA)
OUT2A_SNUB: C500.2 R500.1
OUT2B: R5.1 U2.15(OUTB)
OUT2B_SNUB: C501.2 R501.1
OUT2C: R4.1 U2.16(OUTC)
OUT2C_SNUB: C502.2 R502.1
P3P3V: C38.2 C509.2 C646.2 C652.2 C653.2 C655.2 C660.2 C661.2 C662.2 C663.2 C664.2 C665.2 C674.2 D12.1(ANODE) D13.1(ANODE) D14.1(ANODE) D15.1(ANODE) J23.1 J23.2 J27.12 J27.14 J49.3 J50.3 J51.3 R12.1 R56.1 R57.2 R58.2 R59.2 R71.2 R72.2 R73.2 R504.2 R507.2 R512.1 R515.2 R520.1 R522.1 R528.1 R548.1 R549.1 R600.2 R601.1 R620.1 R637.1 R638.1 R639.1 R640.1 R641.1 R647.1 R696.2 R697.2 R708.2 R709.2 R710.2 R715.2 R716.2 R717.2 R723.2 R726.2 R728.2 R729.2 R730.2 R731.2 R735.1 R737.2 R743.2 R750.2 R752.2 R754.2 R755.2 R760.1 R762.1 R763.2 R765.1 R771.2 R772.2 R774.2 R776.1 U3.4(VDA) U16.3(A2) U16.8(VCC) U18.5(VCC) U20.3(ADD1) U20.4(V+) U20.5(ADD0) U21.21(VCC) U510.5(VCC) U511.5(VDD) U514.5(VCC) U515.24(VCC) U519.8(V+) U520.5(VCC) U521.5(VCC) U522.5(VCC) VR1.3(B) VR2.3(B) ; also on sheet 4 5 6 7 8 9 15 16 17 18 20 21
P3P3V_LP: C41.2 R505.2 R506.2 R727.2 U19.5(VCC) ; also on sheet 9 15 16 17
PIPESTAT0: J27.38 RN504.14
PIPESTAT0R: RN504.3 U11.C6(ETM_PIPESTAT_0)
PIPESTAT1: J27.36 RN504.15
PIPESTAT1R: RN504.2 U11.B5(ETM_PIPESTAT_1)
PIPESTAT2: J27.34 RN504.16
PIPESTAT2R: RN504.1 U11.A4(ETM_PIPESTAT_2)
PMD1K_FB_MOT1: R33.2 U15.11(VM)
PMD1K_FB_MOT2: C1.2 L2.1 U2.11(VM)
PMD1K_GM_IN1: C29.2 R32.2 TP33.1 U15.8(GMIN)
PMD1K_GM_IN2: C511.2 R517.2 TP3.1 U2.8(GMIN)
PMD1K_SENSE_MOT1: R31.1 U15.14(SENSE)
PMD1K_SENSE_MOT2: R6.1 U2.14(SENSE)
PWRGOOD: U18.4(O) U19.1(~{OE}) U500.1(~{OE}) U510.4(O) U518.1(~{OE}) ; also on sheet 8 9 15 17
REAL_CWTACH1: R647.2 U15.5(TACH)
REAL_CWTACH2: R522.2 U2.5(TACH)
RED_LED_EN: J9.1 ; also on sheet 6
RTCK: J23.11 J27.13 R707.1 R709.1
RTCKR: R707.2 U11.E4(RTCK)
SCL0: J49.1 R601.2 U5.6(SCL) U11.A10(IIC0_SCL) U16.6(SCL) U20.1(SCL) U21.23(SCL) ; also on sheet 16 20
SCL1: J50.1 R760.2 U11.D20(GPIO_14) ; also on sheet 20 21
SCL2: J51.1 R512.2 R513.2 ; also on sheet 21
SDA0: J49.2 R549.2 U5.7(SDA) U11.B10(IIC0_SDA) U16.5(SDA) U20.6(SDA) U21.22(SDA) ; also on sheet 16 20
SDA1: J50.2 R762.2 U11.E19(GPIO_15) ; also on sheet 20 21
SDA2: J51.2 R12.2 R13.2 ; also on sheet 21
SEQ_SYNC: R631.2 R632.2 U11.AB9(SEQ_SYNC)
SEQ_SYNC_DUAL: R600.1 R631.1 ; also on sheet 20
SP_CLK: J35.3 R53.2
SP_D0: J35.4 R49.2
SP_D1: J35.5 R54.2
SP_D2: J35.6 R50.2
SP_D3: J35.7 R55.2
SP_D4: J35.8 R51.2
SP_D5: J35.9 R52.2
SP_D6: J35.10 R63.2
SP_D7: J35.11 R62.2
SP_FB: J35.12 R64.2
SP_STAT_IN: R570.2 U515.14(Y10)
SP_WAVE_CLK: U11.G26(GPIO_59) U515.2(A1)
SP_WAVE_D0: R580.2 U515.3(A2)
SP_WAVE_D1: R566.2 U515.4(A3)
SP_WAVE_D2: R569.2 U515.5(A4)
SP_WAVE_D3: R561.2 U515.6(A5)
SP_WAVE_D5: R582.2 U515.8(A7)
SSP0_CSZ5/SPD6: U11.J23(GPIO_66) U515.9(A8) ; also on sheet 18
SSP2_CLK: U11.K23(GPIO_71) ; also on sheet 6
SSP2_CSZ2/SPD7: U11.J24(GPIO_67) U515.10(A9)
SSP2_CSZ_0: U11.J26(GPIO_69) ; also on sheet 6
SSP2_DIN: U11.K24(GPIO_72) ; also on sheet 6
SSP2_DO: U11.J25(GPIO_68) ; also on sheet 6
SWNODE_MOT1: D6.1(C) L7.2 U15.10(VMSW)
SWNODE_MOT2: D3.1(C) L2.2 U2.10(VMSW)
TCK: J23.9 J27.15 J42.5 R710.1 U11.N24(TCK)
TDI: J23.5 J27.19 J42.2 R716.1 U11.N25(TDI)
TDO1: J42.4 U11.N23(TDO1)
TDO2: J23.13 J27.11 R708.1 U11.N22(TDO2)
TILT_X: R514.2 U3.5(DOUT_X)
TILT_Y: R14.2 U3.2(DOUT_Y)
TMS1: J42.3 U11.P25(TMS1)
TMS2: J23.7 J27.17 R715.1 U11.P26(TMS2)
TRACECLK: J27.6 RN504.12
TRACECLKR: RN504.5 U11.D7(ETM_TRACECLK)
TRACEPKT0: J27.30 J28.1 R641.2 RN505.9
TRACEPKT0R: RN505.8 U11.C2(TSTPT_0)
TRACEPKT1: J27.28 J28.2 R640.2 RN505.10
TRACEPKT1R: RN505.7 U11.D3(TSTPT_1)
TRACEPKT2: J27.26 J28.3 R639.2 RN505.11
TRACEPKT2R: RN505.6 U11.E6(TSTPT_2)
TRACEPKT3: J27.24 J28.4 R638.2 RN505.12
TRACEPKT3R: RN505.5 U11.D5(TSTPT_3)
TRACEPKT4: J27.22 J28.5 R637.2 RN505.13
TRACEPKT4R: RN505.4 U11.E7(TSTPT_4)
TRACEPKT5: J27.20 J28.6 RN505.14
TRACEPKT5R: RN505.3 U11.C4(TSTPT_5)
TRACEPKT6: J27.18 J28.7 RN505.15
TRACEPKT6R: RN505.2 U11.B4(TSTPT_6)
TRACEPKT7: J27.16 J28.8 RN505.16
TRACEPKT7R: RN505.1 U11.E8(TSTPT_7)
TRACESYNC: J27.32 RN504.13
TRACESYNCR: RN504.4 U11.A5(ETM_TRACESYNC)
TRSTZ: J27.21 R723.1 U11.M23(TRSTZ) U514.4(O)
TRSTZ_IN: J23.3 J42.1 R717.1 R724.2 U514.1(~{OE})
UART1_CTSZ: U11.E18(GPIO_02) ; also on sheet 9
UART1_RTSZ: U11.A19(GPIO_03) ; also on sheet 9
UART1_RXD: U11.D19(GPIO_01) ; also on sheet 9 21
UART1_TXD: U11.C19(GPIO_00) ; also on sheet 9 21
USB_ENZ: U11.E25(GPIO_38) ; also on sheet 9
N16832566: C26.2 L7.1 R33.1
N16836092: C669.2 J59.1 L505.1 R749.1 R770.2
N16836211: R751.2 TP62.1 U519.3(IN+) VR2.2(WIPER)
N16862598: J48.3 R776.2 R777.2
N16862628: Q504.2(BASE) R668.1
N16862652: R622.2 U508.4(O)
N16862691: R778.2 U524.4(O)
N16862716: C676.2 R765.2 R766.2 U524.5(VCC)
N16862889: C612.2 R618.2 R620.2 U508.5(VCC)
N16862891: J34.2 Q504.3(COLLECTOR) R669.2
N16888382: J47.1 J47.8 R726.1
N16888389: J47.13 R742.1
N16888395: J47.11 R725.1
N16888418: J47.12 R741.1
N16969756: R74.2 R506.1 R507.1 R508.2
N16973926: C516.2 C517.2 R520.2 U5.5(VDD2) U5.8(VDD)
N17028370: R53.1 U515.23(Y1)
N17028379: R49.1 U515.22(Y2)
N17028388: R54.1 U515.21(Y3)
N17028397: R50.1 U515.20(Y4)
N17028406: R55.1 U515.19(Y5)
N17028415: R51.1 U515.18(Y6)
N17028424: R52.1 U515.17(Y7)
N17028433: R63.1 U515.16(Y8)
N17028442: R62.1 U515.15(Y9)
N17028451: R64.1 U515.11(A10)
N17035653: C668.2 J60.1 L504.1 R748.1 R769.2
N17035679: C667.2 J61.1 L503.1 R747.1 R768.2
N17035705: C658.2 J37.1 L502.1 R720.1 R734.2
N17035724: C657.2 J38.1 L501.1 R719.1 R733.2
N17035755: C656.2 J39.1 L500.1 R718.1 R732.2
N17036356: R753.2 TP59.1 U519.5(IN+) VR1.2(WIPER)
N17038227: J52.2 R756.1
N17038557: J53.2 R773.1
N17038579: R773.2 U520.4(O)
N17202061: Q506.1(G) Q507.3(COLLECTOR) R746.1
N17202225: C666.2 J62.1 Q506.3(D)
N17451899: R736.2 SW1.1
N17529082: Q507.2(BASE) R767.2

Not connected (* = marked no-connect by the designer): J23 17* 19*; J27 1* 2* 3* 4* 7* 8* 10* 23* 25* 27* 29* 31* 33* 35* 37*; J62 2*; RN504 6* 7* 8* 9* 10* 11*; U3 1(TOUT)* 6(VREF)*; U5 1(NC)* 4(TEST)*; U16 1(A0)* 2(A1)*; U18 1(~{OE})*; U21 11(GPIOx_10)* 17(GPIOx_16)* 18(GPIOx_17)*

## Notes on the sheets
sheet 10
- NOTE:
  TRSTZ should be pulled down
  for production designs.
- MANUAL RESET JUMPER
- REALVIEW ICE
  JTAG I/F
- INSTALLED
- NOT INSTALLED
- HOLD IN RESET
- NORMAL OPERATION (DEFAULT)
- JTAG BOUNDARY SCAN
- TEST POINT
- ARM TRACE PORT
- Test Points, ARM Trace, JTAG, and Reset
- (C) COPYRIGHT 2023
         Texas Instruments
        All Rights Reserved
sheet 11
- KEYBOARD INTERFACE
- NOTE:
  Do not install when utilizing
  ultra-low power mode
- TILT SENSOR
- NOTE:
  Do not install
  for ultra-low
  power mode.
- TI plans to characterize 2 TILT sensors.
  Only 1 TILT sensor is necessary for
  production designs.
- Projector Settings Memory
  I2C Address set to 0xA8
- TILT SENSOR (I2C)
- I2C Address set to 0x2A
- Temperature Sensor
  I2C Address set to 0x9C
- GPIO Expander and  Keyboard
- (C) COPYRIGHT 2023
         Texas Instruments
        All Rights Reserved
sheet 12
- J8 installed - Hold in Boot Loader
- FORMATTER ONLY I/F
- Note: GPIO_25 can be used as LAMP_SYNC if needed
- BALLAST CONTROL
- GPIO, I2C, and Ballast Control
- (C) COPYRIGHT 2023
         Texas Instruments
        All Rights Reserved
sheet 13
- 3D I/F
- FAN 1
- FAN 4
- DYNAMIC BLACK I/F
- FAN 5
- FAN 2
- 3
- SOT-23
- FAN 3
- FAN 6
- 2
- 1
- 5V FAN
- CW1 INDEX
  SENSOR
- SmoothPicture I/F
- CW2 INDEX
  SENSOR
- Fan, Color Wheel Interface and Peripherals
- (C) COPYRIGHT 2023
         Texas Instruments
        All Rights Reserved
sheet 14
- Note: If not using the motor driver on the
  DLPA100 follow these guidelines for unused pins:
  GMIN (pin 8) – Ground
  OSC (pin 6) – Ground
  SENSE (pin 14) – Ground
  CTAP (pin 13) – VBB
  VM (pin 11) – VBB
  OUTA (pin 12) – No Connect
  OUTB (pin 15) – No Connect
  OUTC (pin 16) – No Connect
  TACH (pin 5) – No Connect
  VMSW (pin 10) – No Connect
  VBB (pin 37) – VBB
- 3
- SOT-323
- 1
- 2
- NOTE:
  R33 is used for current measurement and is not required for
  production units.
- CW1 MOTOR DRIVE
- NOTE: This resistor value is dependant upon the CW motor used.
   The value range is 0.47 ohms to 2.2 ohms.
   The target vlotage range for the SENSE pin is 100-150mV
   when the CW is running at a stable speed.
- CW2 MOTOR DRIVE
- NOTE: This resistor value is dependant upon the CW motor used.
   The value range is 0.47 ohms to 2.2 ohms.
   The target vlotage range for the SENSE pin is 100-150mV
   when the CW is running at a stable speed.
- Color Wheel Drive
- (C) COPYRIGHT 2023
         Texas Instruments
        All Rights Reserved
